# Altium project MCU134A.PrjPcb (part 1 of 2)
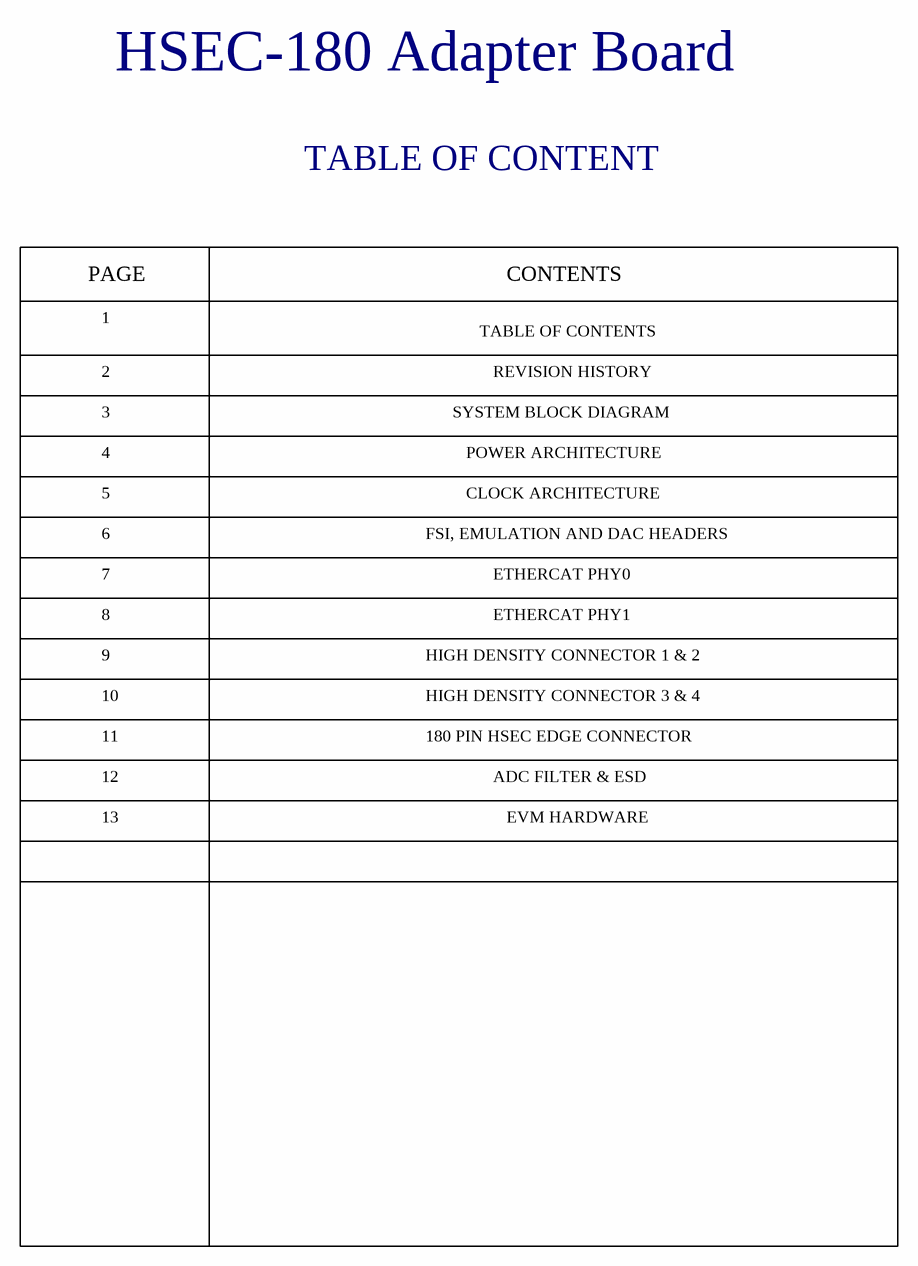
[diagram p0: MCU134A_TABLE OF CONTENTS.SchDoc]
DrawnBy: Texas Instruments; EVM_orderable: HSEC180ADAPEVM; PCB_Rev: A; PRJ_Customer: Public Release; PRJ_Engineer: Martinez Gustavo; PRJ_Number: MCU134; PRJ_Title: HSEC-180 Adapter Board; SCH_REV: A
13 sheets, 219 parts. Net scope: global (net labels, ports and power ports of the same name join across sheets).
Board file: MCU134A.PcbDoc
Sheets:
  MCU134A_TABLE OF CONTENTS.SchDoc
  MCU134A_REVISION_HISTORY.SchDoc
  MCU134A_System_Block_Diagram.SchDoc
  MCU134A_Power_Architecture.SchDoc
  MCU134A_Clock_Architecture.SchDoc
  MCU134A_FSI_Header.SchDoc
  MCU134A_EtherCAT_PHY_0.SchDoc
  MCU134A_EtherCAT_PHY_1.SchDoc
  MCU134A_High_Density_Conn1_2.SchDoc
  MCU134A_High_Density_Conn3_4.SchDoc
  MCU134A_180pin_Edge_Connector.SchDoc
  MCU134A_ADC.SchDoc
  MCU134A_EVM_Hardware.SchDoc

## Sheet MCU134A_TABLE OF CONTENTS.SchDoc
size 431 x 279 mm; Date: Not shown in title block; ApprovedBy: Not shown in title block; CheckedBy: Not shown in title block; Author: Not shown in title block; CompanyName: Not shown in title block; Engineer: Not shown in title block; Organization: Not shown in title block; Address1: Not shown in title block; Address2: Not shown in title block; Address3: Not shown in title block; Address4: Not shown in title block; DocumentNumber: 1; Revision: Use project parameter SCH_Rev; SheetNumber: 1; SheetTotal: 13; PageSetup: Record=PageOptions¦CenterHorizontal=True¦CenterVertical=True¦PrintScale=1.00¦XCorrection=1.00¦YCorrection=1.00¦PrintKind=0¦BorderSize=5000000¦LeftOffset=0¦BottomOffset=0¦Orientation=2¦PaperLength=1000¦PaperWidth=1000¦Scale=100¦PaperSource=15¦PrintQuality=600¦MediaType=1¦DitherType=10¦PaperKind=Letter¦PrintScaleMode=1

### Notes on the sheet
- HSEC-180 Adapter Board
- TABLE OF CONTENT
- PAGE
- 1
- TABLE OF CONTENTS
- CONTENTS
- 2
- REVISION HISTORY
- 3
- 4
- SYSTEM BLOCK DIAGRAM
- POWER ARCHITECTURE
- 5
- 6
- FSI, EMULATION AND DAC HEADERS
- CLOCK ARCHITECTURE
- 7
- ETHERCAT PHY0
- 9
- 8
- HIGH DENSITY CONNECTOR 1 & 2
- ETHERCAT PHY1
- 10
- 11
- HIGH DENSITY CONNECTOR 3 & 4
- 180 PIN HSEC EDGE CONNECTOR
- 12
- ADC FILTER & ESD
- 13
- EVM HARDWARE

## Sheet MCU134A_REVISION_HISTORY.SchDoc
size 431 x 279 mm; Date: Not shown in title block; ApprovedBy: Not shown in title block; CheckedBy: Not shown in title block; Author: Not shown in title block; CompanyName: Not shown in title block; Engineer: Not shown in title block; Organization: Not shown in title block; Address1: Not shown in title block; Address2: Not shown in title block; Address3: Not shown in title block; Address4: Not shown in title block; DocumentNumber: 2; Revision: Use project parameter SCH_Rev; SheetNumber: 2; SheetTotal: 13; PageSetup: Record=PageOptions¦CenterHorizontal=True¦CenterVertical=True¦PrintScale=1.00¦XCorrection=1.00¦YCorrection=1.00¦PrintKind=0¦BorderSize=5000000¦LeftOffset=0¦BottomOffset=0¦Orientation=2¦PaperLength=1000¦PaperWidth=1000¦Scale=100¦PaperSource=15¦PrintQuality=600¦MediaType=1¦DitherType=10¦PaperKind=Letter¦PrintScaleMode=1
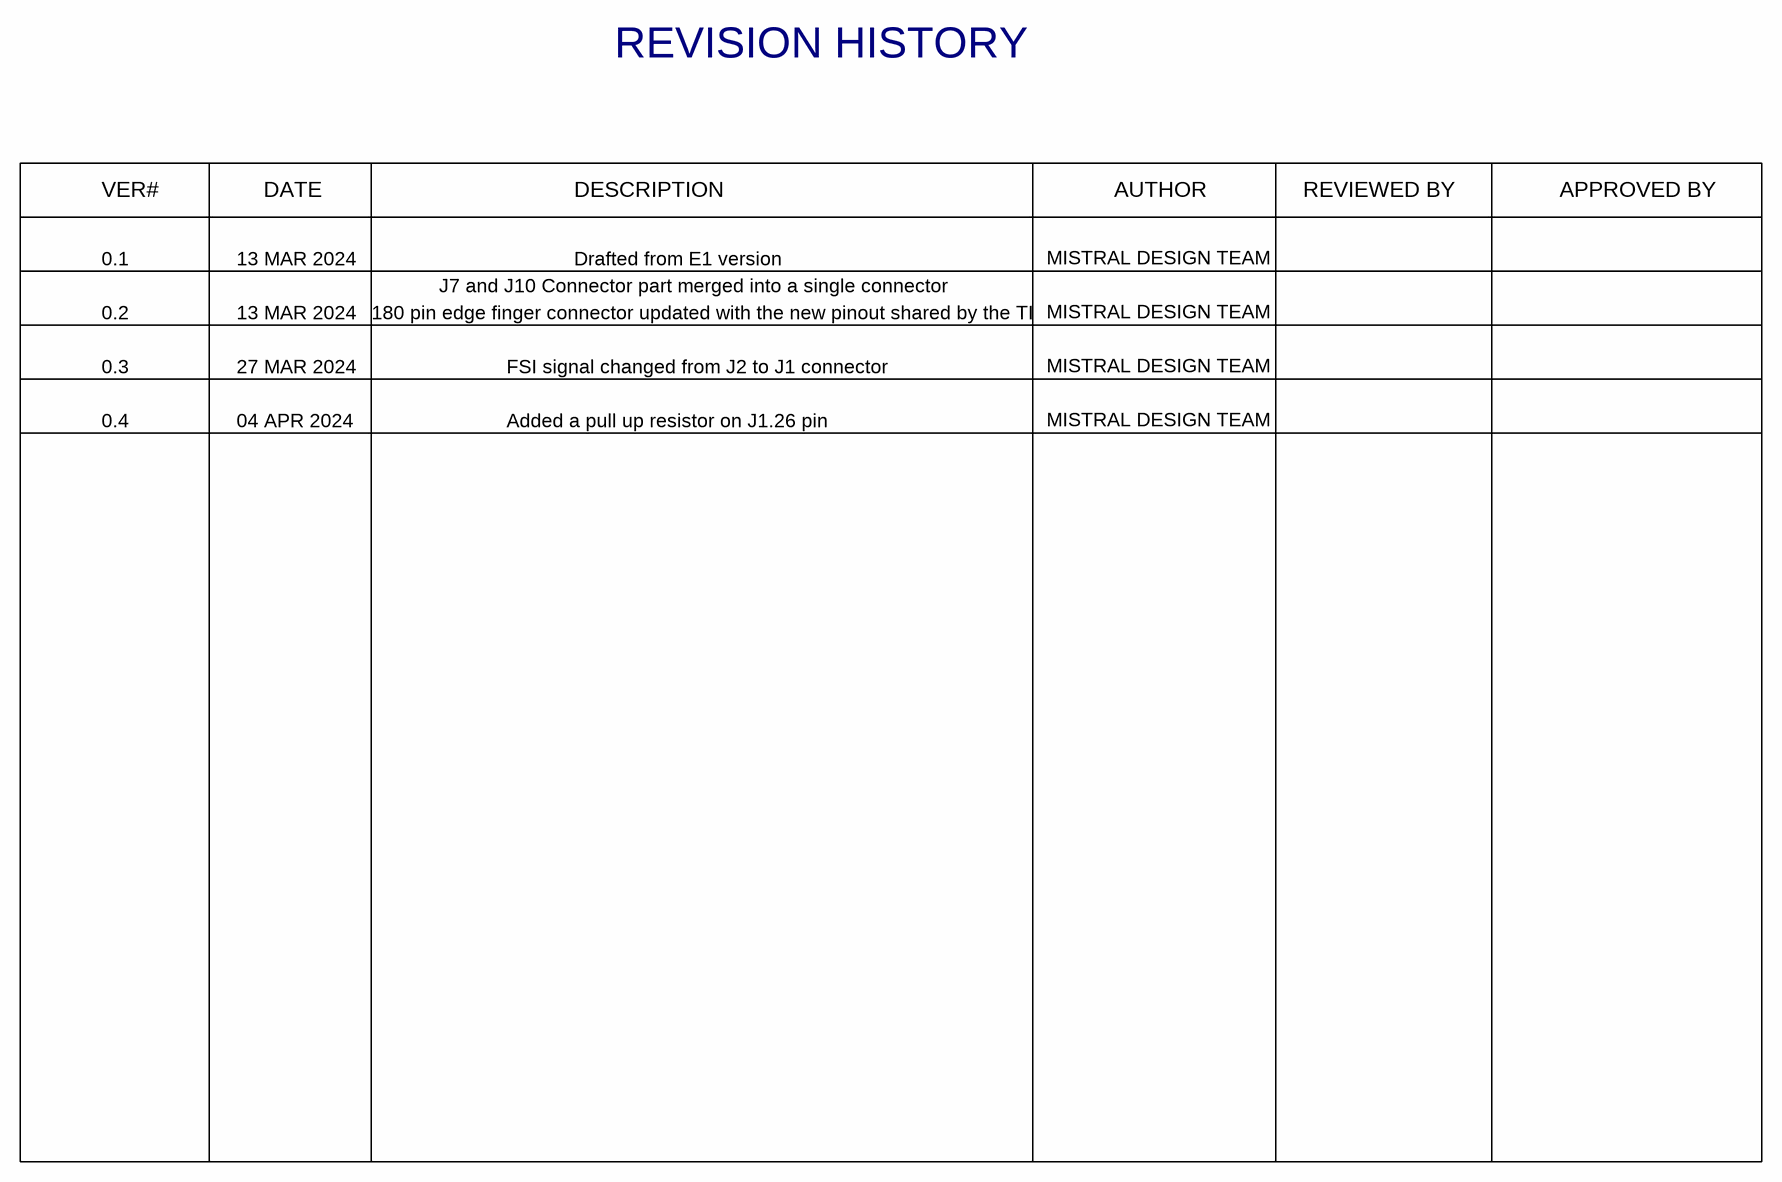
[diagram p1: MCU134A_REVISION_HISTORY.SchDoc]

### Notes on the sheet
- REVISION HISTORY
- VER#
- DATE
- DESCRIPTION
- MISTRAL DESIGN TEAM
- AUTHOR
- REVIEWED BY
- APPROVED BY
- 0.1
- 0.2
- 13 MAR 2024
- 180 pin edge finger connector updated with the new pinout shared by the TI
- J7 and J10 Connector part merged into a single connector
- Drafted from E1 version
- 0.3
- 27 MAR 2024
- FSI signal changed from J2 to J1 connector
- 0.4
- 04 APR 2024
- Added a pull up resistor on J1.26 pin

## Sheet MCU134A_System_Block_Diagram.SchDoc
size 431 x 279 mm; Date: Not shown in title block; ApprovedBy: Not shown in title block; CheckedBy: Not shown in title block; Author: Not shown in title block; CompanyName: Not shown in title block; Engineer: Not shown in title block; Organization: Not shown in title block; Address1: Not shown in title block; Address2: Not shown in title block; Address3: Not shown in title block; Address4: Not shown in title block; DocumentNumber: 3; Revision: Use project parameter SCH_Rev; SheetNumber: 3; SheetTotal: 13; PageSetup: Record=PageOptions¦CenterHorizontal=True¦CenterVertical=True¦PrintScale=1.00¦XCorrection=1.00¦YCorrection=1.00¦PrintKind=0¦BorderSize=5000000¦LeftOffset=0¦BottomOffset=0¦Orientation=2¦PaperLength=1000¦PaperWidth=1000¦Scale=100¦PaperSource=15¦PrintQuality=600¦MediaType=1¦DitherType=10¦PaperKind=Letter¦PrintScaleMode=1
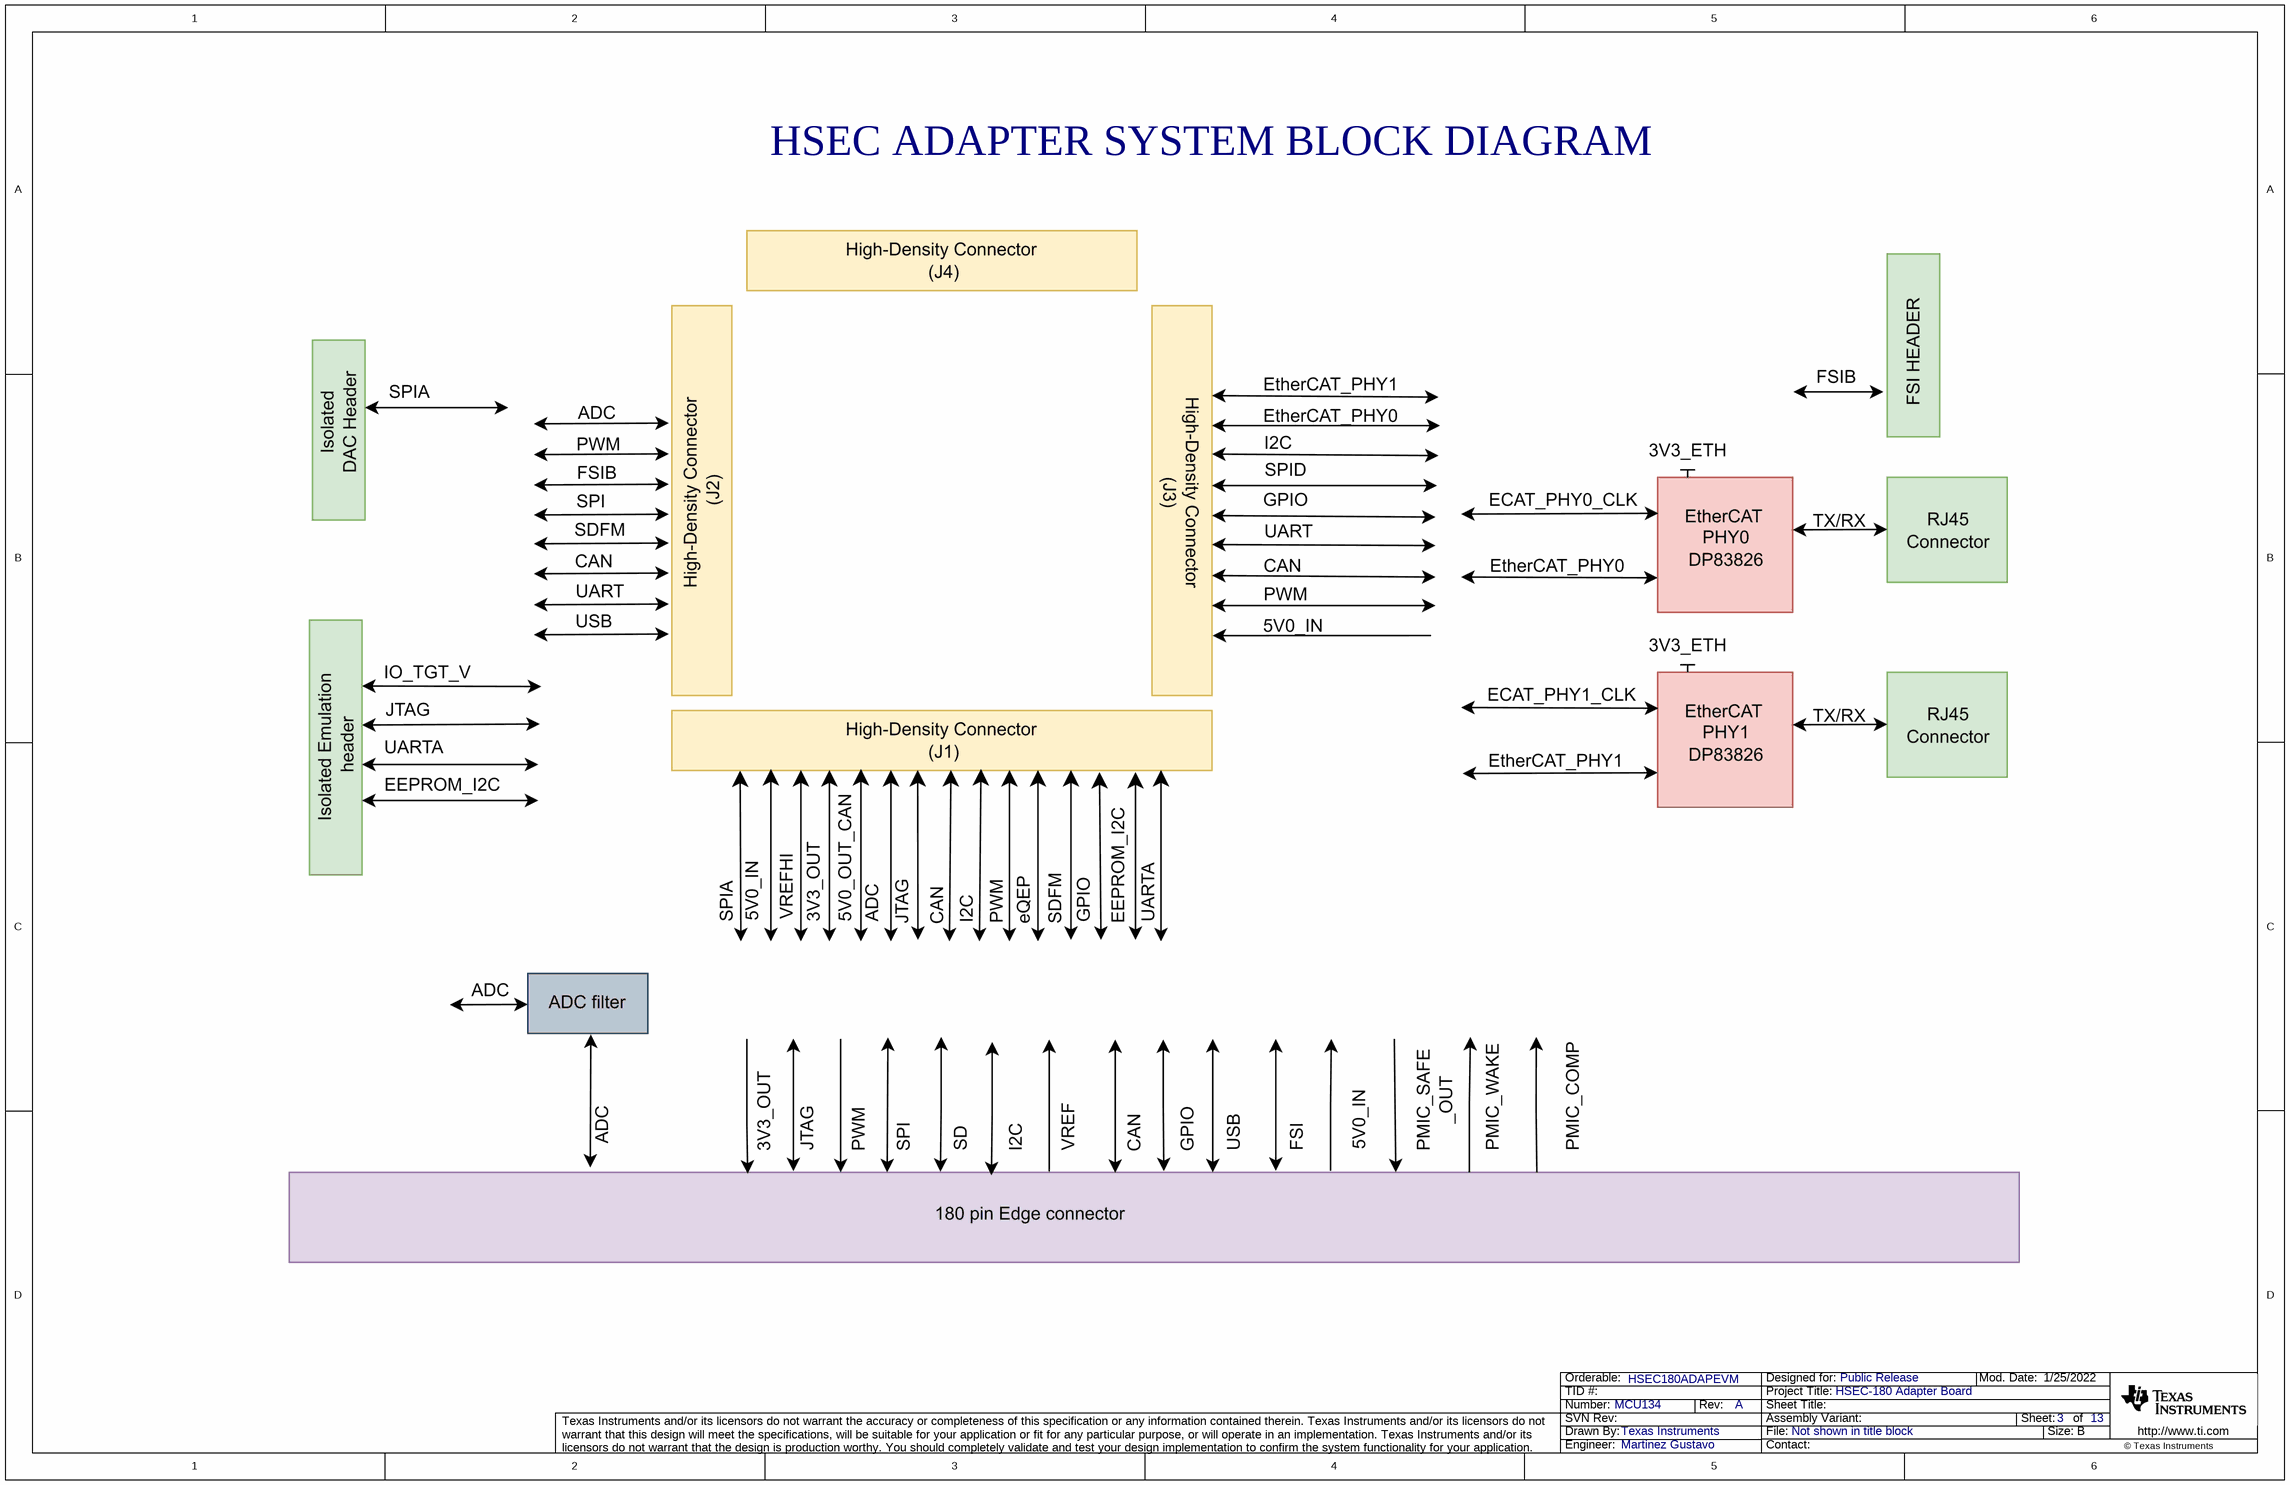
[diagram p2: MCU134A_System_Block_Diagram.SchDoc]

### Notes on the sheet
- HSEC ADAPTER SYSTEM BLOCK DIAGRAM

## Sheet MCU134A_Power_Architecture.SchDoc
size 431 x 279 mm; Date: Not shown in title block; ApprovedBy: Not shown in title block; CheckedBy: Not shown in title block; Author: Not shown in title block; CompanyName: Not shown in title block; Engineer: Not shown in title block; Organization: Not shown in title block; Address1: Not shown in title block; Address2: Not shown in title block; Address3: Not shown in title block; Address4: Not shown in title block; DocumentNumber: 4; Revision: Use project parameter SCH_Rev; SheetNumber: 4; SheetTotal: 13; PageSetup: Record=PageOptions¦CenterHorizontal=True¦CenterVertical=True¦PrintScale=1.00¦XCorrection=1.00¦YCorrection=1.00¦PrintKind=0¦BorderSize=5000000¦LeftOffset=0¦BottomOffset=0¦Orientation=2¦PaperLength=1000¦PaperWidth=1000¦Scale=100¦PaperSource=15¦PrintQuality=600¦MediaType=1¦DitherType=10¦PaperKind=Letter¦PrintScaleMode=1
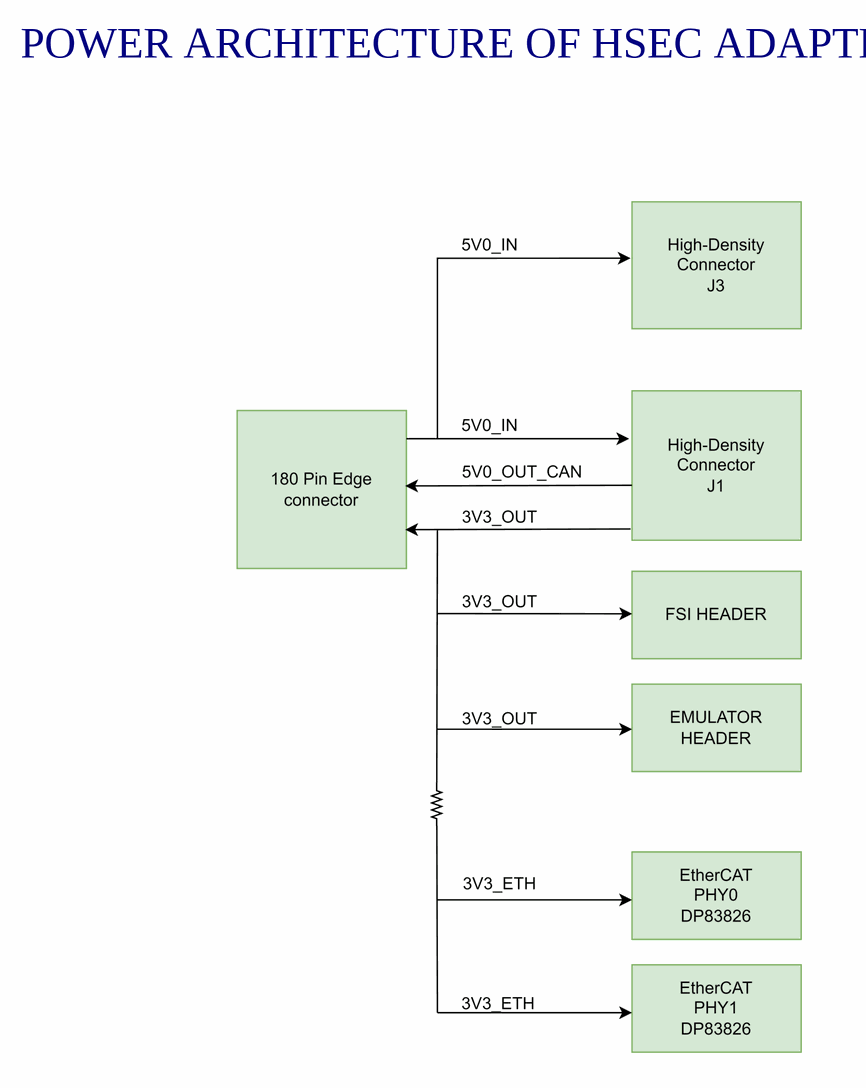
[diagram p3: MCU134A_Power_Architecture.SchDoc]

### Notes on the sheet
- POWER ARCHITECTURE OF HSEC ADAPTER

## Sheet MCU134A_Clock_Architecture.SchDoc
size 431 x 279 mm; Date: Not shown in title block; ApprovedBy: Not shown in title block; CheckedBy: Not shown in title block; Author: Not shown in title block; CompanyName: Not shown in title block; Engineer: Not shown in title block; Organization: Not shown in title block; Address1: Not shown in title block; Address2: Not shown in title block; Address3: Not shown in title block; Address4: Not shown in title block; DocumentNumber: 5; Revision: Use project parameter SCH_Rev; SheetNumber: 5; SheetTotal: 13; PageSetup: Record=PageOptions¦CenterHorizontal=True¦CenterVertical=True¦PrintScale=1.00¦XCorrection=1.00¦YCorrection=1.00¦PrintKind=0¦BorderSize=5000000¦LeftOffset=0¦BottomOffset=0¦Orientation=2¦PaperLength=1000¦PaperWidth=1000¦Scale=100¦PaperSource=15¦PrintQuality=600¦MediaType=1¦DitherType=10¦PaperKind=Letter¦PrintScaleMode=1
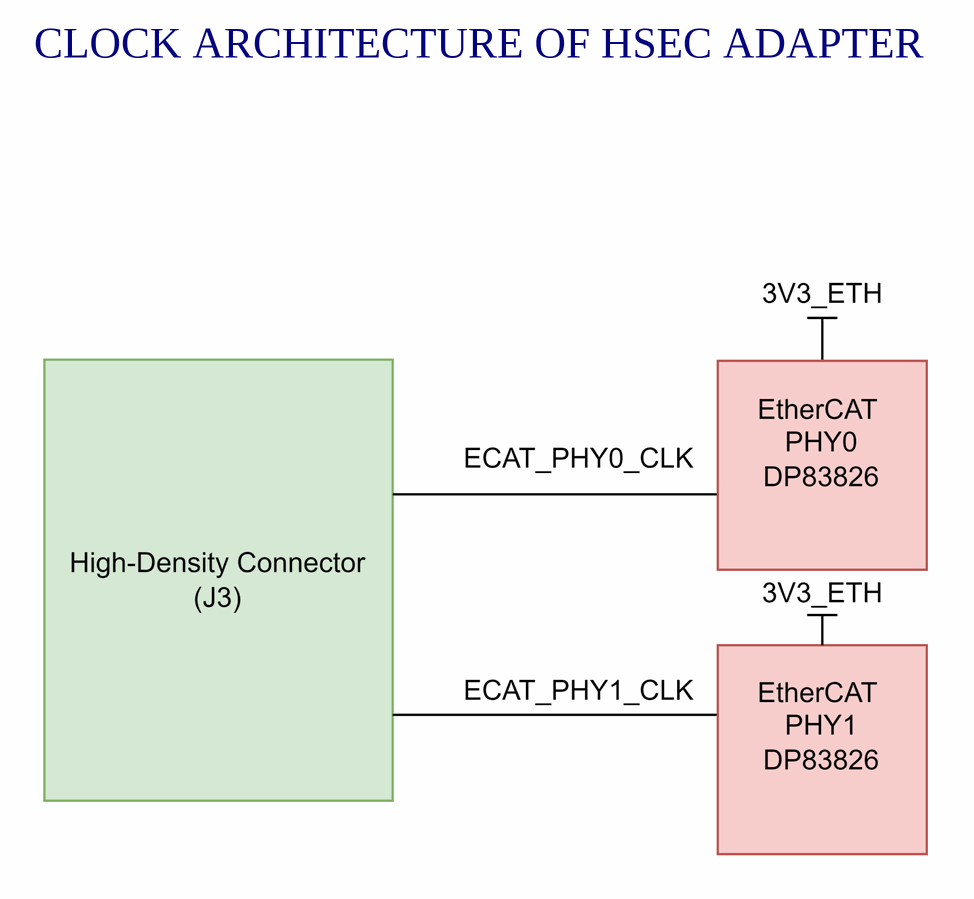
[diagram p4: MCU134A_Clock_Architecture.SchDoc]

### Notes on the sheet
- CLOCK ARCHITECTURE OF HSEC ADAPTER

## Sheet MCU134A_FSI_Header.SchDoc
size 431 x 279 mm; SheetNumber: 6; SheetTotal: 13
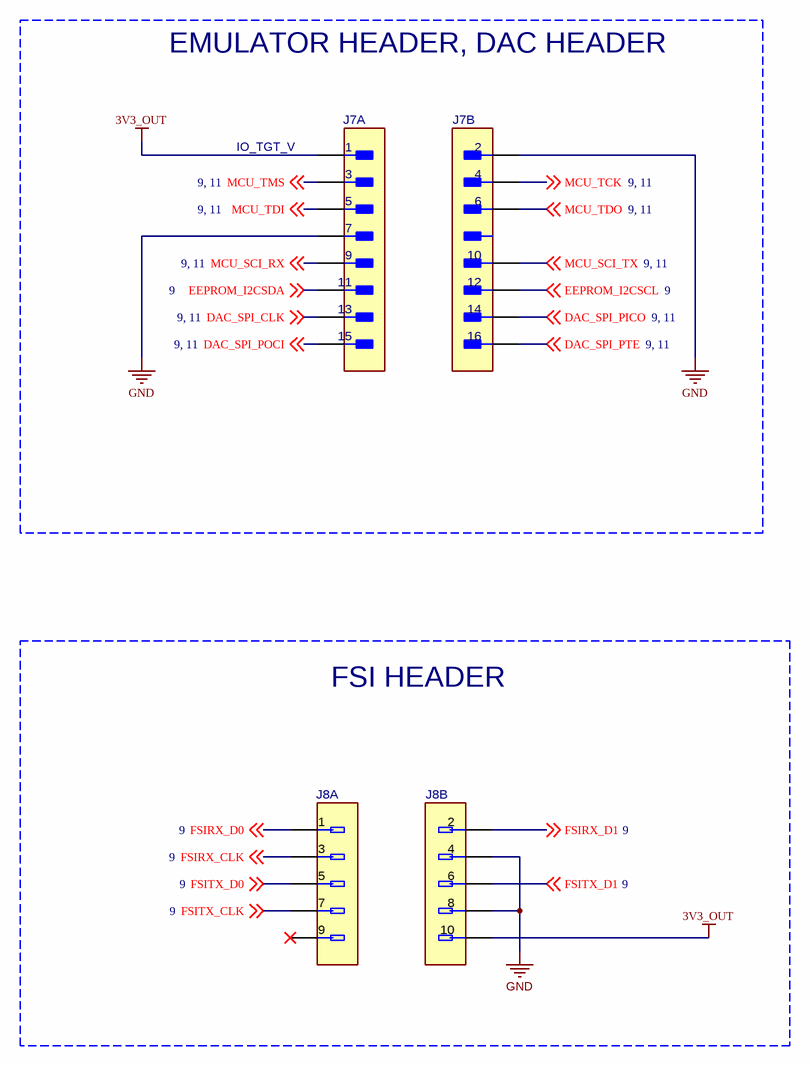
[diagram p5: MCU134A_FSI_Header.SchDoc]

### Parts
J7  TSW-108-08-G-D-RA-008  [FP-TSW-108-08-G-D-RA-008_HDR15-MFG]  (value not drawn)  (parts A,B of 2)
J8  TMM-105-01-T-D  [FP-TMM-105-01-T-D_HDR10-MFG]  (value not drawn)  (parts A,B of 2)

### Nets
3V3_OUT: J7.1 J8.10
GND: J7.2 J7.7 J8.4 J8.8
DAC_SPI_CLK: J7.13 ; off-sheet DAC_SPI_CLK
DAC_SPI_PICO: J7.14 ; off-sheet DAC_SPI_PICO
DAC_SPI_POCI: J7.15 ; off-sheet DAC_SPI_POCI
DAC_SPI_PTE: J7.16 ; off-sheet DAC_SPI_PTE
EEPROM_I2CSCL: J7.12 ; off-sheet EEPROM_I2CSCL
EEPROM_I2CSDA: J7.11 ; off-sheet EEPROM_I2CSDA
FSIRX_CLK: J8.3 ; off-sheet FSIRX_CLK
FSIRX_D0: J8.1 ; off-sheet FSIRX_D0
FSIRX_D1: J8.2 ; off-sheet FSIRX_D1
FSITX_CLK: J8.7 ; off-sheet FSITX_CLK
FSITX_D0: J8.5 ; off-sheet FSITX_D0
FSITX_D1: J8.6 ; off-sheet FSITX_D1
MCU_SCI_RX: J7.9 ; off-sheet MCU_SCI_RX
MCU_SCI_TX: J7.10 ; off-sheet MCU_SCI_TX
MCU_TCK: J7.4 ; off-sheet MCU_TCK
MCU_TDI: J7.5 ; off-sheet MCU_TDI
MCU_TDO: J7.6 ; off-sheet MCU_TDO
MCU_TMS: J7.3 ; off-sheet MCU_TMS

Not connected (* = marked no-connect by the designer): J8 9*

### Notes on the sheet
- EMULATOR HEADER, DAC HEADER
- IO_TGT_V
- FSI HEADER

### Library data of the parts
J7 = CMP-0121702-1: Connector Header Through Hole, Right Angle 16 position 0.100" (2.54mm); Manufacturer: Samtec; ContactFinish: Gold,Nickel; Row_Count: 2; AEC Qualified: No; Conn Gender: Male; SizeZ_mm: 5.21mm
J8 = CMP-0086568-1: Board-To-Board Connector, TMM Series, 10 Contacts, Header, 2 mm, Through Hole, 2 Rows; Manufacturer: Samtec; ContactFinish: Tin,Nickel; Voltage_V: 281V; Symbol Name: SYM-TMM-105-01-T-D; Row_Count: 2; Current_A: 3.2A

## Sheet MCU134A_EtherCAT_PHY_0.SchDoc
size 431 x 279 mm; SheetNumber: 7; SheetTotal: 13
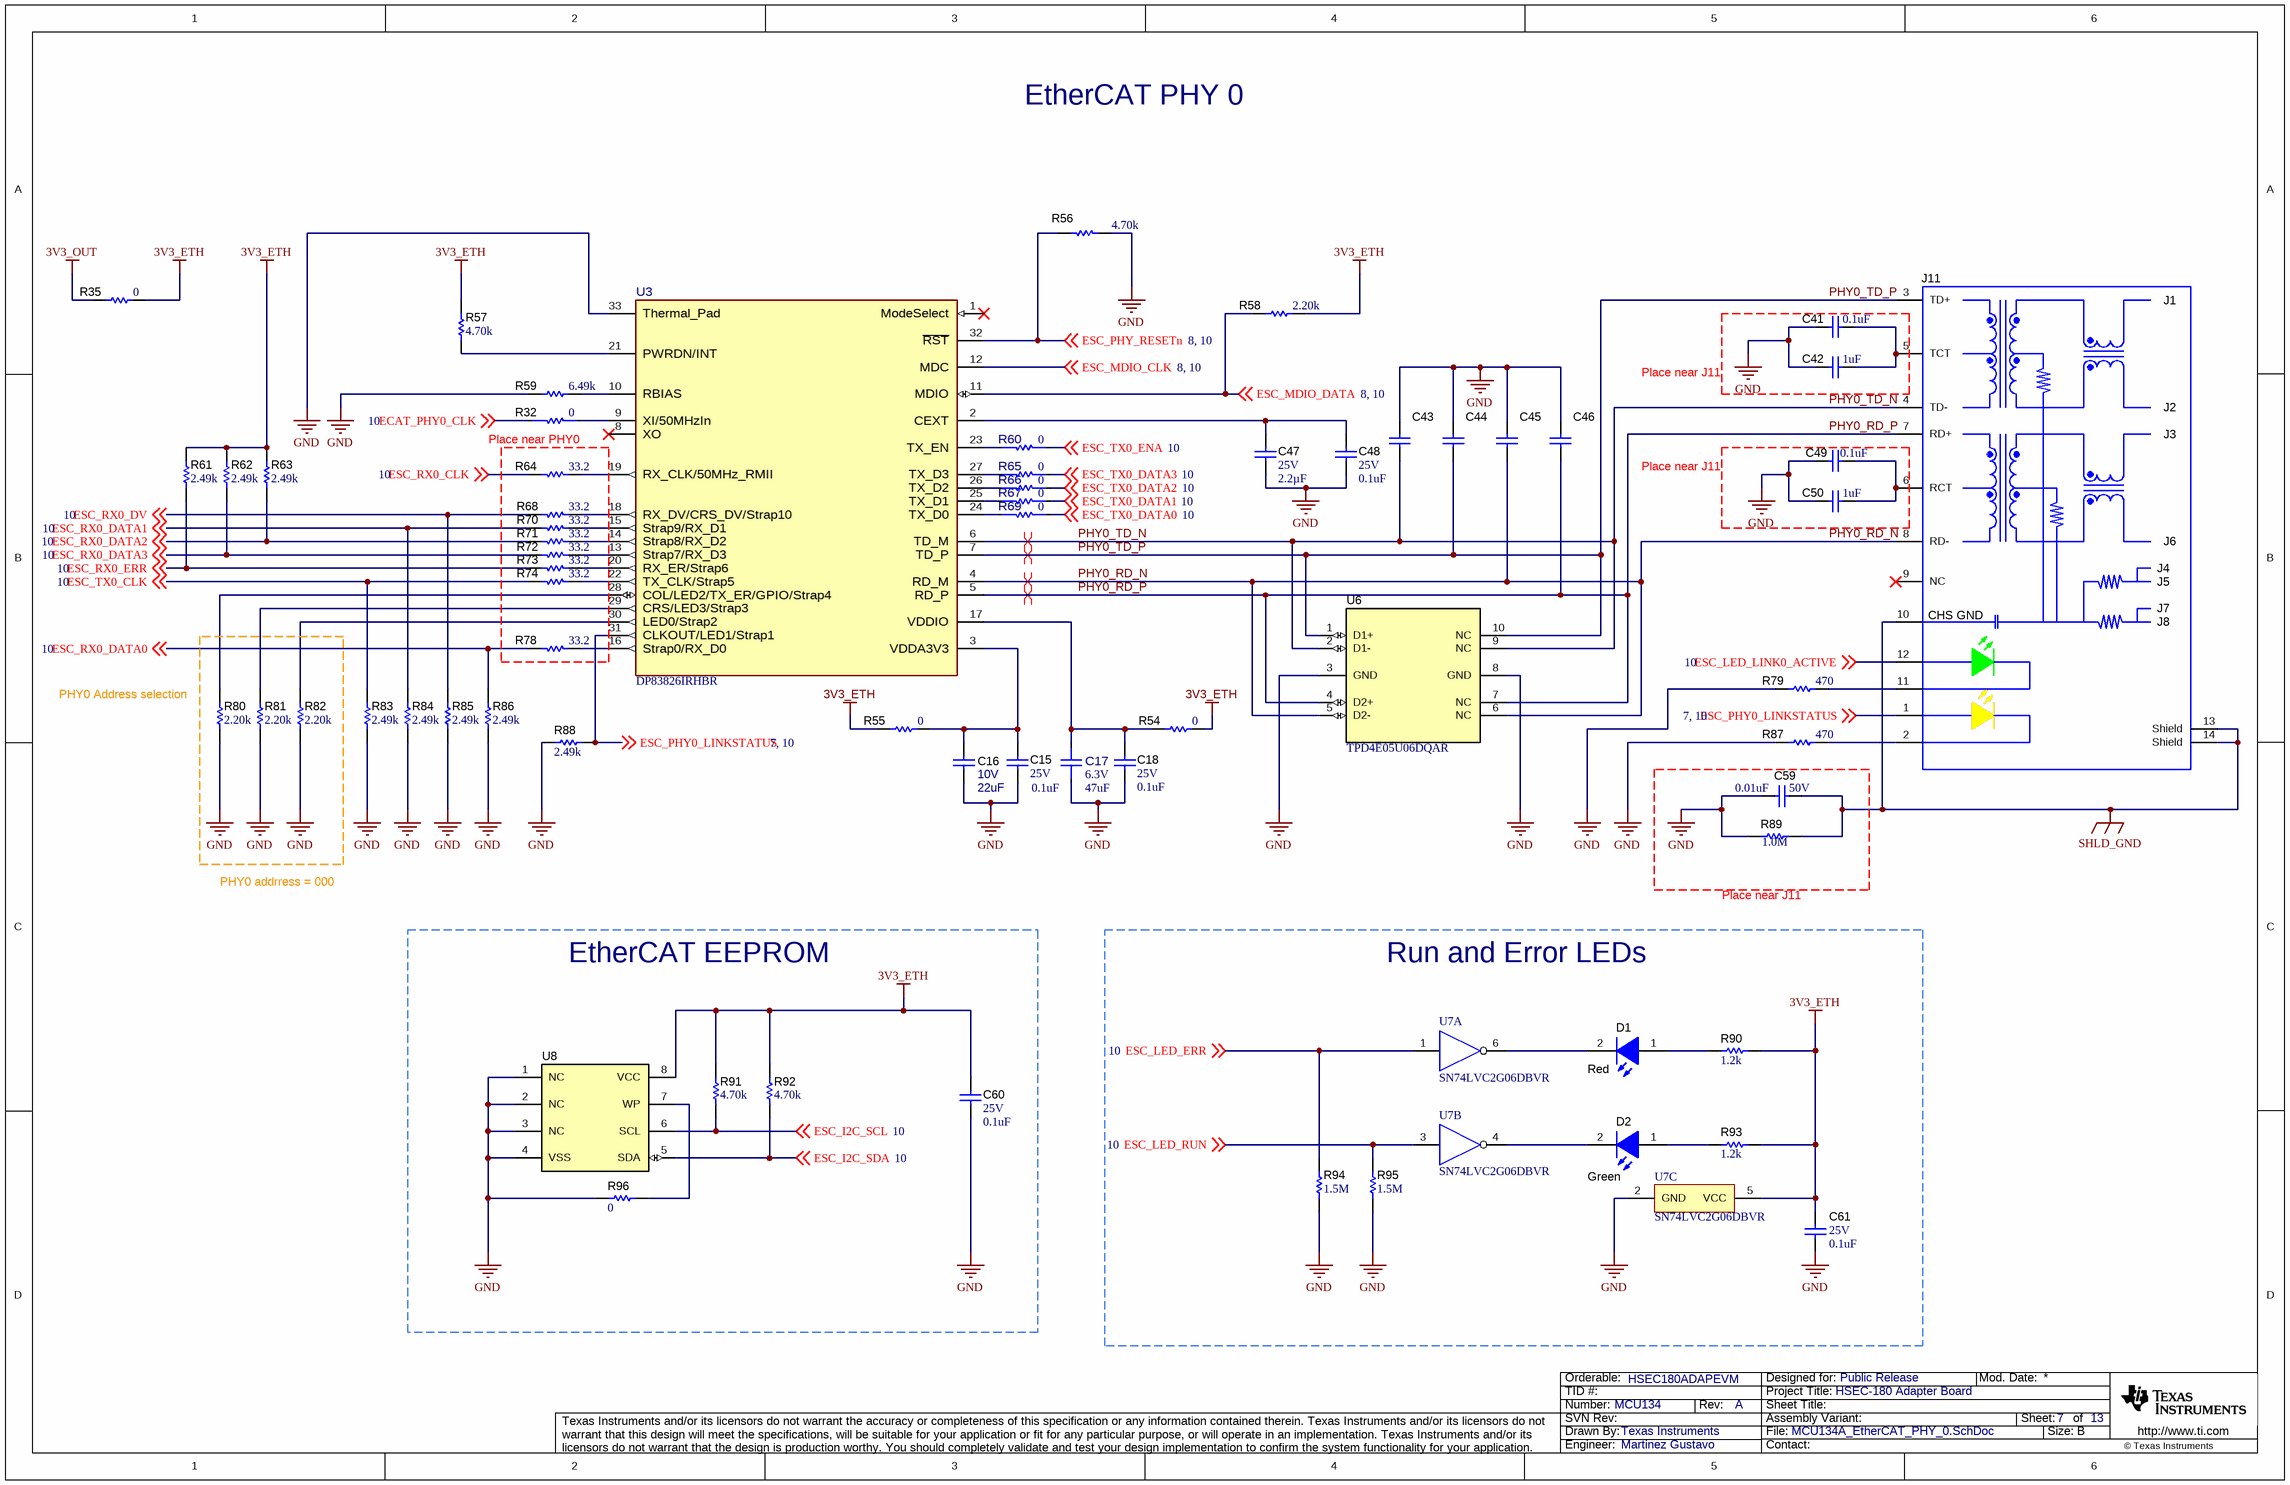
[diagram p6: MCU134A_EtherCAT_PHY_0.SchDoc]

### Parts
C15  VDC_V: 25V  ValueDisplayed: 0.1uF  [0402]  (hidden comment: GRM155R71E104KE14D)
C16  VDC_V: 10V  ValueDisplayed: 22uF  [0603]  (hidden comment: GRM188R61A226ME15D)
C17  VDC_V: 6.3V  ValueDisplayed: 47uF  [FP-GRM188R60J476ME01D_0603-MFG]  (hidden comment: GRM188R60J476ME01D)
C18  VDC_V: 25V  ValueDisplayed: 0.1uF  [0402]  (hidden comment: GRM155R71E104KE14D)
C41  ValueDisplayed: 0.1uF  [0402]  (hidden comment: GRM155R71E104KE14D)
C42  value 1uF  [0402]  (hidden comment: GRM155R61E105KE11D)
C43  GJM1555C1H4R7BB01D  [0402]  (value not drawn)
C44  GJM1555C1H4R7BB01D  [0402]  (value not drawn)
C45  GJM1555C1H4R7BB01D  [0402]  (value not drawn)
C46  GJM1555C1H4R7BB01D  [0402]  (value not drawn)
C47  VDC_V: 25V  ValueDisplayed: 2.2µF  [0402]  (hidden comment: GRM155R61E225ME15D)
C48  VDC_V: 25V  ValueDisplayed: 0.1uF  [0402]  (hidden comment: GRM155R71E104KE14D)
C49  ValueDisplayed: 0.1uF  [0402]  (hidden comment: GRM155R71E104KE14D)
C50  value 1uF  [0402]  (hidden comment: GRM155R61E105KE11D)
C59  VDC_V: 50V  ValueDisplayed: 0.01uF  [0805_HV]  (hidden comment: GRM2195C1H103JA01D)
C60  VDC_V: 25V  ValueDisplayed: 0.1uF  [0402]  (hidden comment: GRM155R71E104KE14D)
C61  VDC_V: 25V  ValueDisplayed: 0.1uF  [0402]  (hidden comment: GRM155R71E104KE14D)
D1  value Red  [APHHS1005_Red]  (hidden comment: APHHS1005SURCK)
D2  value Green  [APHHS1005_Green]  (hidden comment: APHHS1005CGCK)
J11  7498010210A  [Wurth_7498010210A]  (value not drawn)
R32  value 0  [FP-CRCW04020000Z0EDHP_0402-MFG]  (hidden comment: CRCW04020000Z0EDHP)
R35  ValueDisplayed: 0  [0603]  (hidden comment: ERJ-3GEY0R00V)
R54  ValueDisplayed: 0  [0603]  (hidden comment: ERJ-3GEY0R00V)
R55  ValueDisplayed: 0  [0603]  (hidden comment: ERJ-3GEY0R00V)
R56  ValueDisplayed: 4.70k  [0402]  (hidden comment: CRG0402F4K7)
R57  ValueDisplayed: 4.70k  [0402]  (hidden comment: CRG0402F4K7)
R58  ValueDisplayed: 2.20k  [0402]  (hidden comment: CRCW04022K20FKED)
R59  ValueDisplayed: 6.49k  [0402]  (hidden comment: CRCW04026K49FKED)
R60  value 0  [FP-CRCW04020000Z0EDHP_0402-MFG]  (hidden comment: CRCW04020000Z0EDHP)
R61  ValueDisplayed: 2.49k  [0402]  (hidden comment: CRCW04022K49FKED)
R62  ValueDisplayed: 2.49k  [0402]  (hidden comment: CRCW04022K49FKED)
R63  ValueDisplayed: 2.49k  [0402]  (hidden comment: CRCW04022K49FKED)
R64  ValueDisplayed: 33.2  [0402]  (hidden comment: CRCW040233R2FKED)
R65  value 0  [FP-CRCW04020000Z0EDHP_0402-MFG]  (hidden comment: CRCW04020000Z0EDHP)
R66  value 0  [FP-CRCW04020000Z0EDHP_0402-MFG]  (hidden comment: CRCW04020000Z0EDHP)
R67  value 0  [FP-CRCW04020000Z0EDHP_0402-MFG]  (hidden comment: CRCW04020000Z0EDHP)
R68  ValueDisplayed: 33.2  [0402]  (hidden comment: CRCW040233R2FKED)
R69  value 0  [FP-CRCW04020000Z0EDHP_0402-MFG]  (hidden comment: CRCW04020000Z0EDHP)
R70  ValueDisplayed: 33.2  [0402]  (hidden comment: CRCW040233R2FKED)
R71  ValueDisplayed: 33.2  [0402]  (hidden comment: CRCW040233R2FKED)
R72  ValueDisplayed: 33.2  [0402]  (hidden comment: CRCW040233R2FKED)
R73  ValueDisplayed: 33.2  [0402]  (hidden comment: CRCW040233R2FKED)
R74  ValueDisplayed: 33.2  [0402]  (hidden comment: CRCW040233R2FKED)
R78  ValueDisplayed: 33.2  [0402]  (hidden comment: CRCW040233R2FKED)
R79  ValueDisplayed: 470  [0603]  (hidden comment: CRCW0603470RJNEA)
R80  ValueDisplayed: 2.20k  [0402]  (hidden comment: CRCW04022K20FKED)
R81  ValueDisplayed: 2.20k  [0402]  (hidden comment: CRCW04022K20FKED)
R82  ValueDisplayed: 2.20k  [0402]  (hidden comment: CRCW04022K20FKED)
R83  ValueDisplayed: 2.49k  [0402]  (hidden comment: CRCW04022K49FKED)
R84  ValueDisplayed: 2.49k  [0402]  (hidden comment: CRCW04022K49FKED)
R85  ValueDisplayed: 2.49k  [0402]  (hidden comment: CRCW04022K49FKED)
R86  ValueDisplayed: 2.49k  [0402]  (hidden comment: CRCW04022K49FKED)
R87  ValueDisplayed: 470  [0603]  (hidden comment: CRCW0603470RJNEA)
R88  ValueDisplayed: 2.49k  [0402]  (hidden comment: CRCW04022K49FKED)
R89  ValueDisplayed: 1.0M  [0805_HV]  (hidden comment: ERJ-6GEYJ105V)
R90  ValueDisplayed: 1.2k  [0402]  (hidden comment: CRCW04021K20JNED)
R91  ValueDisplayed: 4.70k  [0402]  (hidden comment: CRG0402F4K7)
R92  ValueDisplayed: 4.70k  [0402]  (hidden comment: CRG0402F4K7)
R93  ValueDisplayed: 1.2k  [0402]  (hidden comment: CRCW04021K20JNED)
R94  ValueDisplayed: 1.5M  [0402]  (hidden comment: CRCW04021M50JNED)
R95  ValueDisplayed: 1.5M  [0402]  (hidden comment: CRCW04021M50JNED)
R96  ValueDisplayed: 0  [0402]  (hidden comment: CRCW04020000Z0ED)
U3  DP83826IRHBR  [RHB0032M-MFG]
U6  TPD4E05U06DQAR  [DQA0010A]
U7  SN74LVC2G06DBVR  [DBV0006A_N]  (parts A,B,C of 3)
U8  CAT24C16WI-GT3  [SOIC-8]  (value not drawn)

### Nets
3V3_ETH: C60.1 C61.1 R35.2 R54.2 R55.1 R57.1 R58.1 R61.2 R62.2 R63.2 R90.1 R91.2 R92.2 R93.1 U7.5(VCC) U8.8(VCC)
3V3_OUT: R35.1
GND: C15.2 C16.2 C17.1 C18.2 C41.2 C42.2 C43.1 C44.1 C45.1 C46.1 C47.2 C48.2 C49.2 C50.2 C59.2 C60.2 C61.2 R56.2 R59.1 R79.1 R80.1 R81.1 R82.1 R83.1 R84.1 R85.1 R86.1 R87.1 R88.1 R89.1 R94.2 R95.2 R96.2 U3.33(Thermal_Pad) U6.3(GND) U6.8(GND) U7.2(GND) U8.1(NC) U8.2(NC) U8.3(NC) U8.4(VSS)
SHLD_GND: C59.1 J11.10(CHS_GND) J11.13(Shield) J11.14(Shield) R89.2
ECAT_PHY0_CLK: R32.1 ; off-sheet ECAT_PHY0_CLK
ESC_I2C_SCL: R91.1 U8.6(SCL) ; off-sheet ESC_I2C_SCL
ESC_I2C_SDA: R92.1 U8.5(SDA) ; off-sheet ESC_I2C_SDA
ESC_LED_ERR: R94.1 U7.1(1A) ; off-sheet ESC_LED_ERR
ESC_LED_LINK0_ACTIVE: J11.12(LEFT_LED_ANODE) ; off-sheet ESC_LED_LINK0_ACTIVE
ESC_LED_RUN: R95.1 U7.3(2A) ; off-sheet ESC_LED_RUN
ESC_MDIO_CLK: U3.12(MDC) ; off-sheet ESC_MDIO_CLK
ESC_MDIO_DATA: R58.2 U3.11(MDIO) ; off-sheet ESC_MDIO_DATA
ESC_PHY0_LINKSTATUS: J11.1(RIGHT_LED_ANODE) R88.2 U3.31(CLKOUT/LED1/Strap1) ; off-sheet ESC_PHY0_LINKSTATUS
ESC_PHY_RESETn: R56.1 U3.32(~{RST}) ; off-sheet ESC_PHY_RESETn
ESC_RX0_CLK: R64.1 ; off-sheet ESC_RX0_CLK
ESC_RX0_DATA0: R78.1 R86.2 ; off-sheet ESC_RX0_DATA0
ESC_RX0_DATA1: R70.1 R84.2 ; off-sheet ESC_RX0_DATA1
ESC_RX0_DATA2: R63.1 R71.1 ; off-sheet ESC_RX0_DATA2
ESC_RX0_DATA3: R62.1 R72.1 ; off-sheet ESC_RX0_DATA3
ESC_RX0_DV: R68.1 R85.2 ; off-sheet ESC_RX0_DV
ESC_RX0_ERR: R61.1 R73.1 ; off-sheet ESC_RX0_ERR
ESC_TX0_CLK: R74.1 R83.2 ; off-sheet ESC_TX0_CLK
ESC_TX0_DATA0: R69.2 ; off-sheet ESC_TX0_DATA0
ESC_TX0_DATA1: R67.2 ; off-sheet ESC_TX0_DATA1
ESC_TX0_DATA2: R66.2 ; off-sheet ESC_TX0_DATA2
ESC_TX0_DATA3: R65.2 ; off-sheet ESC_TX0_DATA3
ESC_TX0_ENA: R60.2 ; off-sheet ESC_TX0_ENA
PHY0_RD_N: C45.2 J11.8(RD-) U3.4(RD_M) U6.5(D2-) U6.6(NC)
PHY0_RD_P: C46.2 J11.7(RD+) U3.5(RD_P) U6.4(D2+) U6.7(NC)
PHY0_TD_N: C43.2 J11.4(TD-) U3.6(TD_M) U6.2(D1-) U6.9(NC)
PHY0_TD_P: C44.2 J11.3(TD+) U3.7(TD_P) U6.1(D1+) U6.10(NC)
NetC15_1: C15.1 C16.1 R55.2 U3.3(VDDA3V3)
NetC17_2: C17.2 C18.1 R54.1 U3.17(VDDIO)
NetC41_1: C41.1 C42.1 J11.5(TCT)
NetC47_1: C47.1 C48.1 U3.2(CEXT)
NetC49_1: C49.1 C50.1 J11.6(RCT)
NetD1_1: D1.1(A) R90.2
NetD1_2: D1.2(K) U7.6(1Y)
NetD2_1: D2.1(A) R93.2
NetD2_2: D2.2(K) U7.4(2Y)
NetJ11_2: J11.2(RIGHT_LED_CATHODE) R87.2
NetJ11_11: J11.11(LEFT_LED_CATHODE) R79.2
NetR32_2: R32.2 U3.9(XI/50MHzIn)
NetR57_2: R57.2 U3.21(PWRDN/INT)
NetR59_2: R59.2 U3.10(RBIAS)
NetR60_1: R60.1 U3.23(TX_EN)
NetR64_2: R64.2 U3.19(RX_CLK/50MHz_RMII)
NetR65_1: R65.1 U3.27(TX_D3)
NetR66_1: R66.1 U3.26(TX_D2)
NetR67_1: R67.1 U3.25(TX_D1)
NetR68_2: R68.2 U3.18(RX_DV/CRS_DV/Strap10)
NetR69_1: R69.1 U3.24(TX_D0)
NetR70_2: R70.2 U3.15(Strap9/RX_D1)
NetR71_2: R71.2 U3.14(Strap8/RX_D2)
NetR72_2: R72.2 U3.13(Strap7/RX_D3)
NetR73_2: R73.2 U3.20(RX_ER/Strap6)
NetR74_2: R74.2 U3.22(TX_CLK/Strap5)
NetR78_2: R78.2 U3.16(Strap0/RX_D0)
NetR80_2: R80.2 U3.28(COL/LED2/TX_ER/GPIO/Strap4)
NetR81_2: R81.2 U3.29(CRS/LED3/Strap3)
NetR82_2: R82.2 U3.30(LED0/Strap2)
NetR96_1: R96.1 U8.7(WP)

Not connected (* = marked no-connect by the designer): J11 9(NC)*; U3 1(ModeSelect)* 8(XO)*

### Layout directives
differential pair: PHY0_RD_N, PHY0_RD_P, PHY0_TD_N, PHY0_TD_P

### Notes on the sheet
- EtherCAT PHY 0
- Place near J11
- (near R32) Place near PHY0
- (near R80) PHY0 Address selection
- PHY0 addrress = 000
- EtherCAT EEPROM
- Run and Error LEDs

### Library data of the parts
C15 C18 C48 C60 C61 = CMP-0006659-2: CAP, CERM, 0.1 uF, 25 V, +/- 10%, X7R, 0402; Manufacturer: MuRata; TaMin_C: -55°C; Polarized: N; SizeAreaWB_mm2: 3; Value1: Unknown; U/M: EA; Value: 0.1uF; TaMax_C: 125°C; SizeZ_mm: 0.6; SizeX_mm: 1; SizeY_mm: 0.5; Cap_F: 100nF; AEC Category: Q200
C16 = CMP-0007324-5: CAP, CERM, 22 uF, 10 V, +/- 20%, X5R, 0603; Manufacturer: MuRata; TaMin_C: -55°C; Polarized: N; SizeAreaWB_mm2: 4.68; Value1: Unknown; U/M: EA; Value: 22uF; TaMax_C: 85°C; SizeZ_mm: 1; SizeX_mm: 1.6; SizeY_mm: 0.8; SizeArea_mm2: 1.28; Cap_F: 22µF; AEC Category: Q200
C17 = CMP-0120208-1: Chip Multilayer Ceramic Capacitor for General Purpose 47uF ±20% 6.3V X5R SMD 0603; Manufacturer: Murata; TempCo: 15%; Value: 47µF; SizeZ_mm: 1mm; AEC Qualified: No
C41 C49 = CMP-0006659-2: CAP, CERM, 0.1 uF, 25 V, +/- 10%, X7R, 0402; Manufacturer: MuRata; TaMin_C: -55°C; Polarized: N; SizeAreaWB_mm2: 3; Value1: Unknown; U/M: EA; Value: 0.1uF; TaMax_C: 125°C; SizeZ_mm: 0.6; SizeX_mm: 1; SizeY_mm: 0.5; Value2: 25V; Cap_F: 100nF; AEC Category: Q200
C42 C50 = CMP-0086061-1: CAP, CERM, 1 µF, 25 V,+/- 10%, X5R, 0402; Manufacturer: MuRata; SizeY_mm: 0.5; TaMin_C: -55°C; VDC_V: 25V; Polarized: N; AEC Category: Q200; Cap_F: 1µF; SizeX_mm: 1; SizeAreaWB_mm2: 3; SizeZ_mm: 0.6; TaMax_C: 85°C; U/M: EA
C43-C46 = CMP-0006367-2: CAP, CERM, 4.7 pF, 50 V, +/- 2%, C0G/NP0, 0402; Manufacturer: MuRata; Value: 4.7pF; SizeZ_mm: 0.6; VDC_V: 50V; AEC Qualified: N; AEC Category: Q200; SizeArea_mm2: 0.5; SizeAreaWB_mm2: 3; SizeX_mm: 1; TaMax_C: 125°C; TaMin_C: -55°C; U/M: EA; Value1: Unknown
C47 = CMP-0081010-1: CAP, CERM, 2.2 µF, 25 V,+/- 20%, X5R, 0402; Manufacturer: MuRata; TaMin_C: -55°C; Polarized: N; SizeAreaWB_mm2: 3; U/M: EA; Value: 2.2uF; TaMax_C: 85°C; SizeZ_mm: 0.6; SizeX_mm: 1; SizeY_mm: 0.5; AEC Category: Q200
C59 = CMP-0008156-2: CAP, CERM, 0.01 uF, 50 V, +/- 5%, C0G/NP0, 0805; Manufacturer: MuRata; TaMin_C: -55°C; Polarized: N; SizeAreaWB_mm2: 6.75; Value1: Unknown; U/M: EA; Value: 0.01uF; TaMax_C: 125°C; SizeZ_mm: 1.45; SizeX_mm: 2; SizeY_mm: 1.25; Cap_Case: 0805; SizeArea_mm2: 2.5; Cap_F: 10nF; AEC Category: Q200
D1 = CMP-0067681-2: LED, Red, SMD; Manufacturer: Kingbright; Vf_V: 1.95V; SizeAreaWB_mm2: 3.0; Tjmax_C: 85°C; SizeX_mm: 1.0; Io_A: 20mA; SizeArea_mm2: 0.5; Vr_V: 5V; Value1: 0.075W; SizeZ_mm: 0.6; Angle: 120.0; Ir_A: 10µA; Power_TotalModule: 75mW
D2 = CMP-0067682-2: LED, Green, SMD; Manufacturer: Kingbright; Value1: 0.075W; Vf_V: 2.1V; Vr_V: 5V; SizeArea_mm2: 0.5; Power_TotalModule: 75mW; Tjmax_C: 85°C; Angle: 120.0; SizeAreaWB_mm2: 3.0; SizeX_mm: 1.0; Ir_A: 10µA; Io_A: 20mA; SizeZ_mm: 0.6
J11 = CMP-0086350-1: Connector, RJ45, 1x1, Gold, R/A, SMT; Manufacturer: Wurth Elektronik; Row_Count: 1; Gender: Female
R32 R60 R65-R67 R69 = CMP-0001606-1: RES Thick Film, 0Ω, 0.2W, 0402; Manufacturer: Vishay Dale; AEC Grade: Grade 0; AEC Qualified: Yes; Power_W: 200mW; SizeZ_mm: 0.4mm; VDC_V: 50V
R35 R54 R55 = CMP-0025874-4: RES, 0, 5%, 0.1 W, AEC-Q200 Grade 0, 0603; Manufacturer: Panasonic; Power_W: 100mW; TempCo: 600 ppm/C; Value_Code: 0000; Value: 0; EIA_Code: E24; SizeX_mm: 1.6; SizeY_mm: 0.8; SizeZ_mm: 1; Value2: 0.1W; SizeArea_mm2: 1.28; AEC Qualified: Y; VDC_V: 50V; AEC Category: Q200; SizeAreaWB_mm2: 4.68
R56 R57 R91 R92 = CMP-0026631-1: RES, 4.70 k, 1%, 0.063 W, 0402; Manufacturer: TE Connectivity; Power_W: 63mW; TempCo: 100 ppm/C; Value_Code: 4k70; U/M: EA; Value: 4.70k; Res_ohm: 4.7k; SizeX_mm: 1; SizeY_mm: 0.5; SizeZ_mm: 0.6; Value2: 0.063W; AEC Qualified: N; AEC Category: Q200
R58 R80-R82 = CMP-0026231-2: RES, 2.20 k, 1%, 0.063 W, AEC-Q200 Grade 0, 0402; Manufacturer: Vishay-Dale; Power_W: 63mW; TempCo: 100 ppm/C; Value_Code: 2k20; Value: 2.20k; Res_ohm: 2.2k; SizeX_mm: 1; SizeY_mm: 0.5; SizeZ_mm: 0.6; Value2: 0.063W; AEC Qualified: Y; AEC Category: Q200; AEC Grade: 0
R59 = CMP-0026515-2: RES, 6.49 k, 1%, 0.063 W, AEC-Q200 Grade 0, 0402; Manufacturer: Vishay-Dale; Power_W: 63mW; TempCo: 100 ppm/C; Value_Code: 6k49; Value: 6.49k; EIA_Code: E96; SizeX_mm: 1; SizeY_mm: 0.5; SizeZ_mm: 0.6; Value2: 0.063W; AEC Qualified: Y; VDC_V: 50V; AEC Category: Q200; AEC Grade: 0
R61-R63 R83-R86 R88 = CMP-0026237-2: RES, 2.49 k, 1%, 0.063 W, AEC-Q200 Grade 0, 0402; Manufacturer: Vishay-Dale; Power_W: 63mW; TempCo: 100 ppm/C; Value_Code: 2k49; Value: 2.49k; EIA_Code: E96; SizeX_mm: 1; SizeY_mm: 0.5; SizeZ_mm: 0.6; Value2: 0.063W; AEC Qualified: Y; VDC_V: 50V; AEC Category: Q200; AEC Grade: 0
R64 R68 R70-R74 R78 = CMP-0026299-2: RES, 33.2, 1%, 0.063 W, AEC-Q200 Grade 0, 0402; Manufacturer: Vishay-Dale; Power_W: 63mW; TempCo: 100 ppm/C; Value_Code: 33R2; Value: 33.2; EIA_Code: E96; SizeX_mm: 1; SizeY_mm: 0.5; SizeZ_mm: 0.6; Value2: 0.063W; AEC Qualified: Y; VDC_V: 50V; AEC Category: Q200; AEC Grade: 0
R79 R87 = CMP-0025813-4: RES, 470, 5%, 0.1 W, AEC-Q200 Grade 0, 0603; Manufacturer: Vishay-Dale; Power_W: 100mW; TempCo: 200 ppm/C; Value_Code: 470R; Value: 470; EIA_Code: E24; SizeX_mm: 1.6; SizeY_mm: 0.8; SizeZ_mm: 1; Value2: 0.1W; SizeArea_mm2: 1.28; AEC Qualified: Y; VDC_V: 75V; AEC Category: Q200; AEC Grade: 0
R89 = CMP-0020623-3: RES, 1.0 M, 5%, 0.125 W, AEC-Q200 Grade 0, 0805; Manufacturer: Panasonic; Power_W: 125mW; TempCo: 150 ppm/C; Value_Code: 1M00; Value: 1.0Meg; EIA_Code: E24; Res_ohm: 1M; SizeX_mm: 2; SizeY_mm: 1.25; SizeZ_mm: 1.45; Value2: 0.125W; SizeArea_mm2: 2.5; AEC Qualified: Y; VDC_V: 150V; AEC Category: Q200; AEC Grade: 0; SizeAreaWB_mm2: 6.75
R90 R93 = CMP-0026854-5: RES, 1.2 k, 5%, 0.063 W, AEC-Q200 Grade 0, 0402; Manufacturer: Vishay-Dale; Power_W: 63mW; TempCo: 200 ppm/C; Value_Code: 1k20; Value: 1.2k; EIA_Code: E24; SizeX_mm: 1; SizeY_mm: 0.5; SizeZ_mm: 0.6; Value2: 0.063W; AEC Qualified: Y; VDC_V: 50V; AEC Category: Q200; AEC Grade: 0
R94 R95 = CMP-0026863-2: RES, 1.5 M, 5%, 0.063 W, AEC-Q200 Grade 0, 0402; Manufacturer: Vishay-Dale; Power_W: 63mW; TempCo: 200 ppm/C; Value_Code: 1M50; Value: 1.5Meg; EIA_Code: E24; SizeX_mm: 1; SizeY_mm: 0.5; SizeZ_mm: 0.6; Value2: 0.063W; AEC Qualified: Y; VDC_V: 50V; AEC Category: Q200; AEC Grade: 0
R96 = CMP-0026822-3: RES, 0, 5%, 0.063 W, AEC-Q200 Grade 0, 0402; Manufacturer: Vishay-Dale; Power_W: 63mW; TempCo: 200 ppm/C; Value_Code: 0000; Value: 0; EIA_Code: E24; SizeX_mm: 1; SizeY_mm: 0.5; SizeZ_mm: 0.6; Value2: 0.063W; AEC Qualified: Y; VDC_V: 50V; AEC Category: Q200
U3 = CMP-0001411-1: Ethernet PHY 10BASE-Te/00BASE-TX 10/100 Mbps 160mW 1.8V/3.3V 2-Pin VQFN Industrial; Manufacturer: Texas Instruments; SizeZ_mm: 1mm; AEC Qualified: No; Data Rate: 100Mbits/s; Max Supply Voltage: 3.6V; Min Supply Voltage: 1.62V; Number Of Channels: 1; Simplex Duplex: Full-Duplex; Standoff Height: 0mm; TaMax_C: +85°C; TaMin_C: -40°C
U6 = CMP-0073613-3: 4-Channel Ultra-Low-Capacitance IEC ESD Protection Diode, DQA0010A (USON-10); Alternate Manufacturer: Texas Instruments; Green_Lifecycle: Active; SizeAreaWB_mm2: 7.0; Green_REACh: Passed; SizeZ_mm: 0.55; SizeX_mm: 1.0; SizeY_mm: 2.5; CompType: IC; AEC Category: Q200; AEC Qualified: N
U7 = CMP-0051777-2: Dual Inverter Buffer/Driver with Open-Drain Output, DBV0006A, LARGE T&R; Manufacturer: Texas Instruments; Technology Family: LVC; Input Type: CMOS/TTL; Output Drive (IOL/IOH)(Max)(mA): 32/-32; tpd @ Nom Voltage(Max)(ns): 8.2,4.4,3.9,3.4; Voltage(Nom)(V): 1.8,2.5,3.3,5; 3-State Output: No; Rating: Catalog; Sub-Family: Inverting Buffer/Driver; Logic: Inverting; VCC(Min)(V): 1.65; F @ Nom Voltage(Max)(Mhz): 150; Output Type: CMOS; ICC @ Nom Voltage(Max)(mA): 0.01; Bits(#): 2; VCC(Max)(V): 5.5
U8 = CMP-0082059-1: 16 Kb I2C EEPROM Serial, SOIC-8; Manufacturer: ON Semiconductor; SizeArea_mm2: 29.351; SizeAreaWB_mm2: 55.131; SizeY_mm: 4.9; SizeZ_mm: 1.75; SizeX_mm: 5.99

## Sheet MCU134A_EtherCAT_PHY_1.SchDoc
size 431 x 279 mm; SheetNumber: 8; SheetTotal: 13
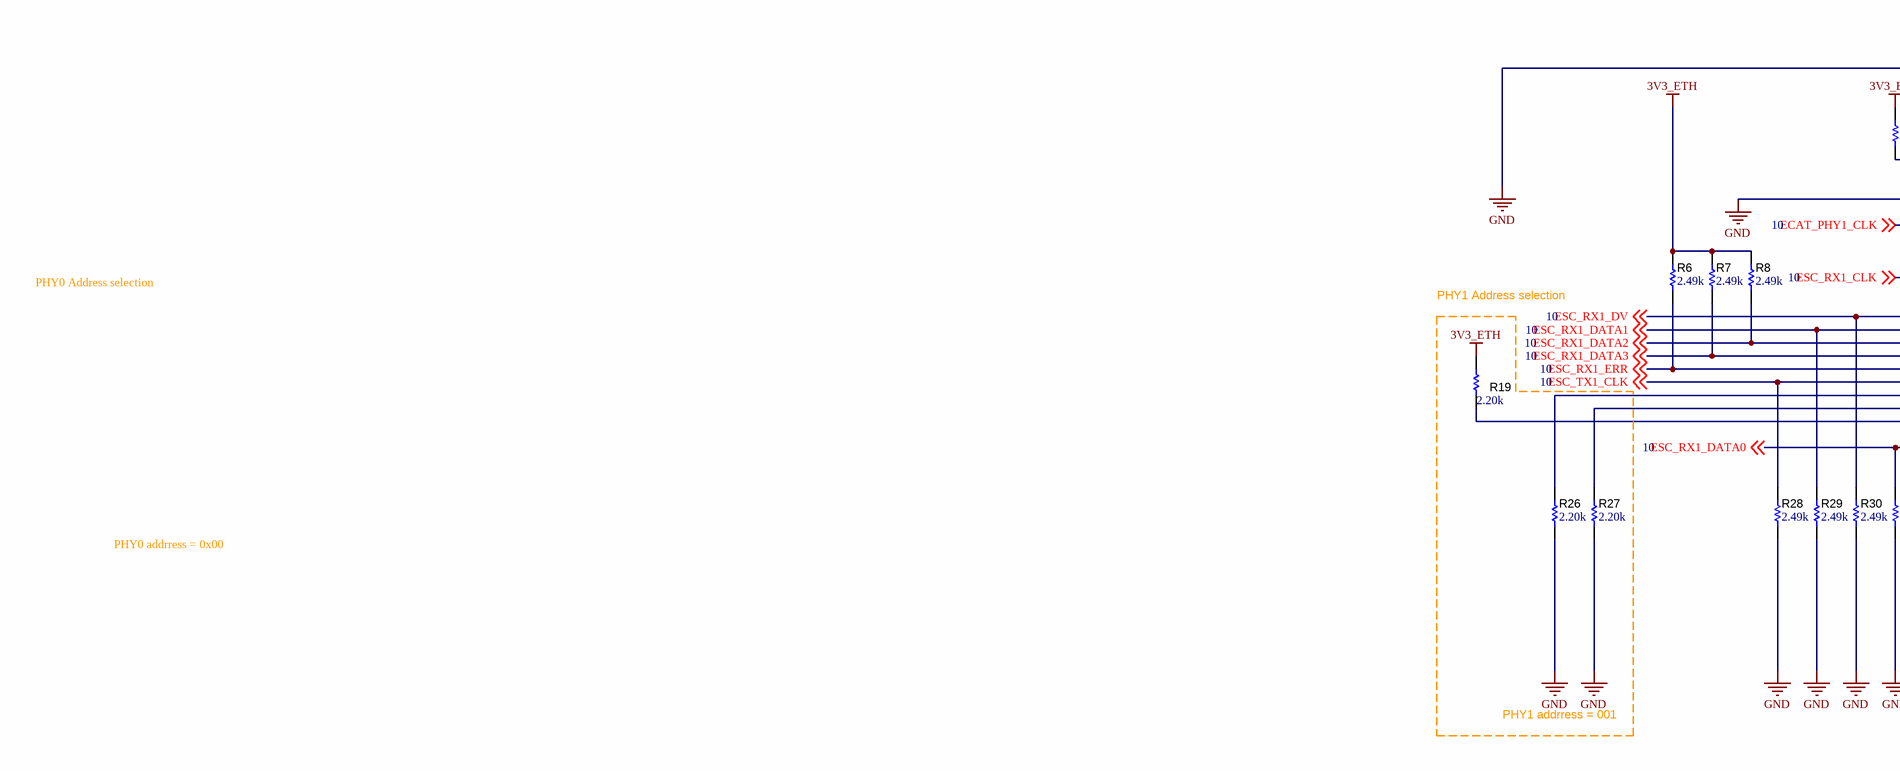
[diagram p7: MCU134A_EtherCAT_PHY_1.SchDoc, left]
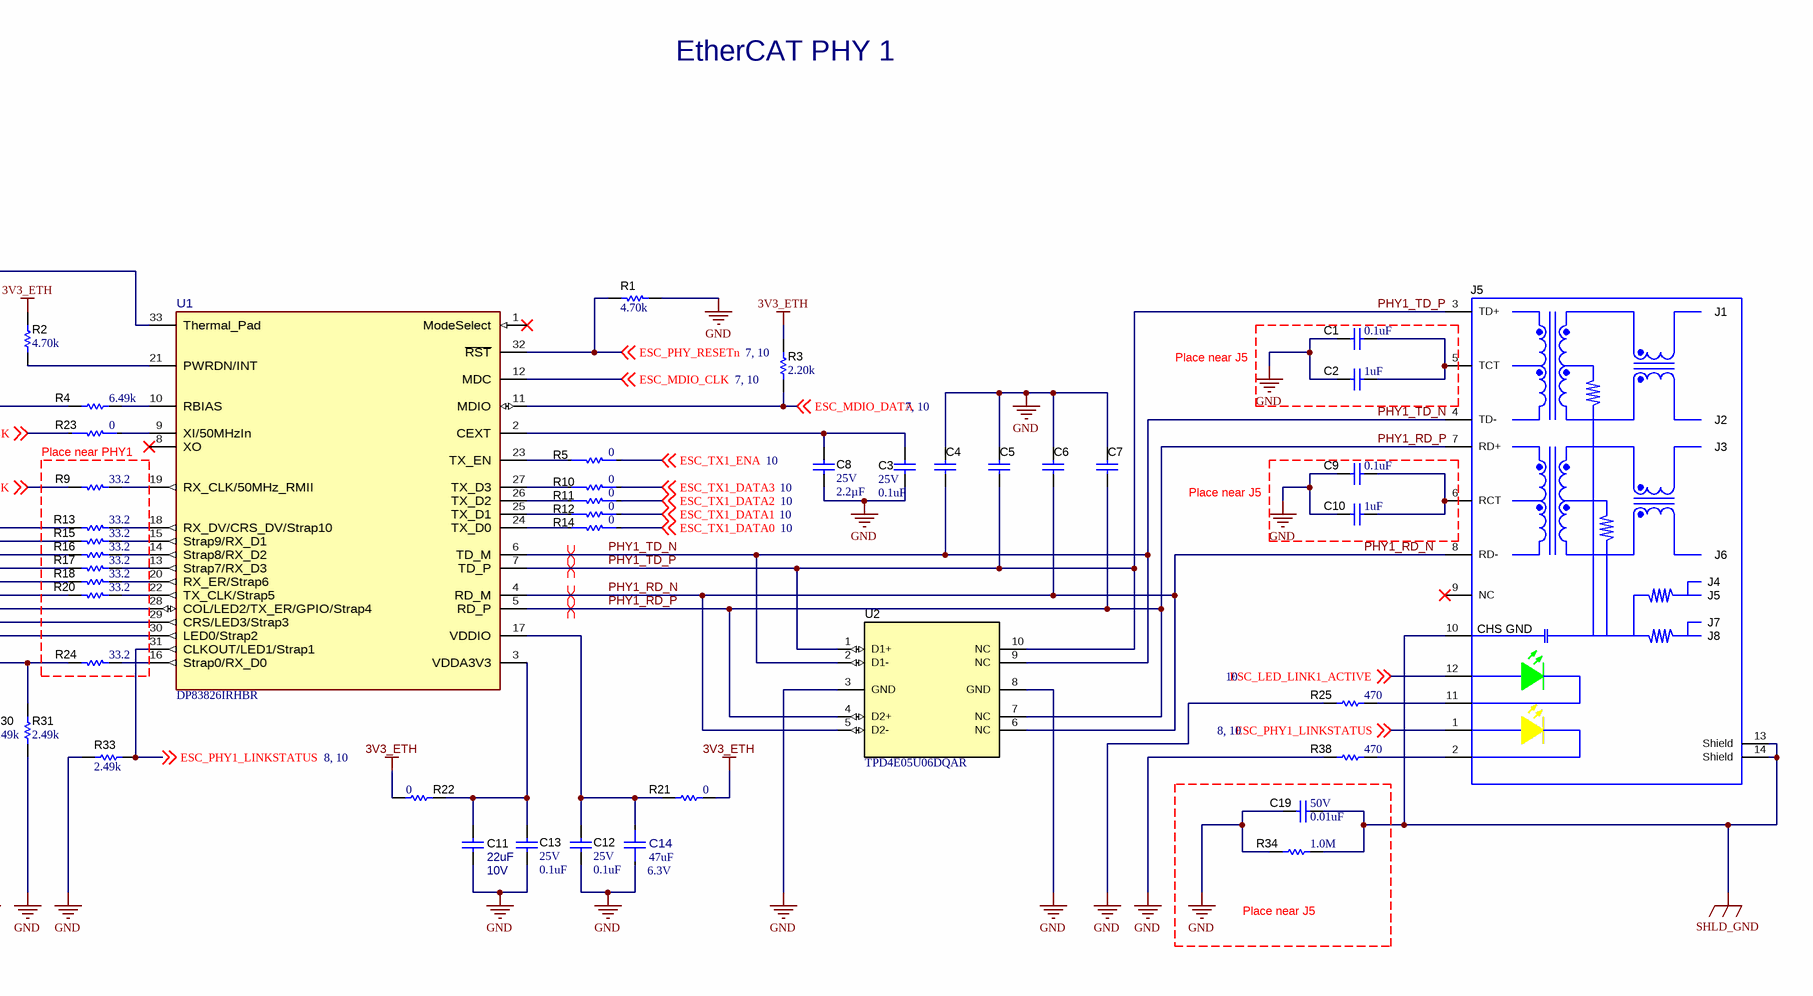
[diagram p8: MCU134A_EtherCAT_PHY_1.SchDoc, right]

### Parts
C1  ValueDisplayed: 0.1uF  [0402]  (hidden comment: GRM155R71E104KE14D)
C2  value 1uF  [0402]  (hidden comment: GRM155R61E105KE11D)
C3  VDC_V: 25V  ValueDisplayed: 0.1uF  [0402]  (hidden comment: GRM155R71E104KE14D)
C4  GJM1555C1H4R7BB01D  [0402]  (value not drawn)
C5  GJM1555C1H4R7BB01D  [0402]  (value not drawn)
C6  GJM1555C1H4R7BB01D  [0402]  (value not drawn)
C7  GJM1555C1H4R7BB01D  [0402]  (value not drawn)
C8  VDC_V: 25V  ValueDisplayed: 2.2µF  [0402]  (hidden comment: GRM155R61E225ME15D)
C9  ValueDisplayed: 0.1uF  [0402]  (hidden comment: GRM155R71E104KE14D)
C10  value 1uF  [0402]  (hidden comment: GRM155R61E105KE11D)
C11  Value2: 10V  ValueDisplayed: 22uF  [0603]  (hidden comment: GRM188R61A226ME15D)
C12  VDC_V: 25V  ValueDisplayed: 0.1uF  [0402]  (hidden comment: GRM155R71E104KE14D)
C13  VDC_V: 25V  ValueDisplayed: 0.1uF  [0402]  (hidden comment: GRM155R71E104KE14D)
C14  VDC_V: 6.3V  ValueDisplayed: 47uF  [FP-GRM188R60J476ME01D_0603-MFG]  (hidden comment: GRM188R60J476ME01D)
C19  VDC_V: 50V  ValueDisplayed: 0.01uF  [0805_HV]  (hidden comment: GRM2195C1H103JA01D)
J5  7498010210A  [Wurth_7498010210A]  (value not drawn)
R1  ValueDisplayed: 4.70k  [0402]  (hidden comment: CRG0402F4K7)
R2  ValueDisplayed: 4.70k  [0402]  (hidden comment: CRG0402F4K7)
R3  ValueDisplayed: 2.20k  [0402]  (hidden comment: CRCW04022K20FKED)
R4  ValueDisplayed: 6.49k  [0402]  (hidden comment: CRCW04026K49FKED)
R5  value 0  [FP-CRCW04020000Z0EDHP_0402-MFG]  (hidden comment: CRCW04020000Z0EDHP)
R6  ValueDisplayed: 2.49k  [0402]  (hidden comment: CRCW04022K49FKED)
R7  ValueDisplayed: 2.49k  [0402]  (hidden comment: CRCW04022K49FKED)
R8  ValueDisplayed: 2.49k  [0402]  (hidden comment: CRCW04022K49FKED)
R9  ValueDisplayed: 33.2  [0402]  (hidden comment: CRCW040233R2FKED)
R10  value 0  [FP-CRCW04020000Z0EDHP_0402-MFG]  (hidden comment: CRCW04020000Z0EDHP)
R11  value 0  [FP-CRCW04020000Z0EDHP_0402-MFG]  (hidden comment: CRCW04020000Z0EDHP)
R12  value 0  [FP-CRCW04020000Z0EDHP_0402-MFG]  (hidden comment: CRCW04020000Z0EDHP)
R13  ValueDisplayed: 33.2  [0402]  (hidden comment: CRCW040233R2FKED)
R14  value 0  [FP-CRCW04020000Z0EDHP_0402-MFG]  (hidden comment: CRCW04020000Z0EDHP)
R15  ValueDisplayed: 33.2  [0402]  (hidden comment: CRCW040233R2FKED)
R16  ValueDisplayed: 33.2  [0402]  (hidden comment: CRCW040233R2FKED)
R17  ValueDisplayed: 33.2  [0402]  (hidden comment: CRCW040233R2FKED)
R18  ValueDisplayed: 33.2  [0402]  (hidden comment: CRCW040233R2FKED)
R19  ValueDisplayed: 2.20k  [0402]  (hidden comment: CRCW04022K20FKED)
R20  ValueDisplayed: 33.2  [0402]  (hidden comment: CRCW040233R2FKED)
R21  ValueDisplayed: 0  [0603]  (hidden comment: ERJ-3GEY0R00V)
R22  ValueDisplayed: 0  [0603]  (hidden comment: ERJ-3GEY0R00V)
R23  value 0  [FP-CRCW04020000Z0EDHP_0402-MFG]  (hidden comment: CRCW04020000Z0EDHP)
R24  ValueDisplayed: 33.2  [0402]  (hidden comment: CRCW040233R2FKED)
R25  ValueDisplayed: 470  [0603]  (hidden comment: CRCW0603470RJNEA)
R26  ValueDisplayed: 2.20k  [0402]  (hidden comment: CRCW04022K20FKED)
R27  ValueDisplayed: 2.20k  [0402]  (hidden comment: CRCW04022K20FKED)
R28  ValueDisplayed: 2.49k  [0402]  (hidden comment: CRCW04022K49FKED)
R29  ValueDisplayed: 2.49k  [0402]  (hidden comment: CRCW04022K49FKED)
R30  ValueDisplayed: 2.49k  [0402]  (hidden comment: CRCW04022K49FKED)
R31  ValueDisplayed: 2.49k  [0402]  (hidden comment: CRCW04022K49FKED)
R33  ValueDisplayed: 2.49k  [0402]  (hidden comment: CRCW04022K49FKED)
R34  ValueDisplayed: 1.0M  [0805_HV]  (hidden comment: ERJ-6GEYJ105V)
R38  ValueDisplayed: 470  [0603]  (hidden comment: CRCW0603470RJNEA)
U1  DP83826IRHBR  [RHB0032M-MFG]
U2  TPD4E05U06DQAR  [DQA0010A]

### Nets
3V3_ETH: R2.1 R3.2 R6.2 R7.2 R8.2 R19.2 R21.2 R22.1
GND: C1.2 C2.2 C3.2 C4.1 C5.1 C6.1 C7.1 C8.2 C9.2 C10.2 C11.2 C12.2 C13.2 C14.1 C19.2 R1.2 R4.1 R25.1 R26.1 R27.1 R28.1 R29.1 R30.1 R31.1 R33.1 R34.1 R38.1 U1.33(Thermal_Pad) U2.3(GND) U2.8(GND)
SHLD_GND: C19.1 J5.10(CHS_GND) J5.13(Shield) J5.14(Shield) R34.2
ECAT_PHY1_CLK: R23.1 ; off-sheet ECAT_PHY1_CLK
ESC_LED_LINK1_ACTIVE: J5.12(LEFT_LED_ANODE) ; off-sheet ESC_LED_LINK1_ACTIVE
ESC_MDIO_CLK: U1.12(MDC) ; off-sheet ESC_MDIO_CLK
ESC_MDIO_DATA: R3.1 U1.11(MDIO) ; off-sheet ESC_MDIO_DATA
ESC_PHY1_LINKSTATUS: J5.1(RIGHT_LED_ANODE) R33.2 U1.31(CLKOUT/LED1/Strap1) ; off-sheet ESC_PHY1_LINKSTATUS
ESC_PHY_RESETn: R1.1 U1.32(~{RST}) ; off-sheet ESC_PHY_RESETn
ESC_RX1_CLK: R9.1 ; off-sheet ESC_RX1_CLK
ESC_RX1_DATA0: R24.1 R31.2 ; off-sheet ESC_RX1_DATA0
ESC_RX1_DATA1: R15.1 R29.2 ; off-sheet ESC_RX1_DATA1
ESC_RX1_DATA2: R8.1 R16.1 ; off-sheet ESC_RX1_DATA2
ESC_RX1_DATA3: R7.1 R17.1 ; off-sheet ESC_RX1_DATA3
ESC_RX1_DV: R13.1 R30.2 ; off-sheet ESC_RX1_DV
ESC_RX1_ERR: R6.1 R18.1 ; off-sheet ESC_RX1_ERR
ESC_TX1_CLK: R20.1 R28.2 ; off-sheet ESC_TX1_CLK
ESC_TX1_DATA0: R14.2 ; off-sheet ESC_TX1_DATA0
ESC_TX1_DATA1: R12.2 ; off-sheet ESC_TX1_DATA1
ESC_TX1_DATA2: R11.2 ; off-sheet ESC_TX1_DATA2
ESC_TX1_DATA3: R10.2 ; off-sheet ESC_TX1_DATA3
ESC_TX1_ENA: R5.2 ; off-sheet ESC_TX1_ENA
PHY1_RD_N: C6.2 J5.8(RD-) U1.4(RD_M) U2.5(D2-) U2.6(NC)
PHY1_RD_P: C7.2 J5.7(RD+) U1.5(RD_P) U2.4(D2+) U2.7(NC)
PHY1_TD_N: C4.2 J5.4(TD-) U1.6(TD_M) U2.2(D1-) U2.9(NC)
PHY1_TD_P: C5.2 J5.3(TD+) U1.7(TD_P) U2.1(D1+) U2.10(NC)
NetC1_1: C1.1 C2.1 J5.5(TCT)
NetC3_1: C3.1 C8.1 U1.2(CEXT)
NetC9_1: C9.1 C10.1 J5.6(RCT)
NetC11_1: C11.1 C13.1 R22.2 U1.3(VDDA3V3)
NetC12_1: C12.1 C14.2 R21.1 U1.17(VDDIO)
NetJ5_2: J5.2(RIGHT_LED_CATHODE) R38.2
NetJ5_11: J5.11(LEFT_LED_CATHODE) R25.2
NetR2_2: R2.2 U1.21(PWRDN/INT)
NetR4_2: R4.2 U1.10(RBIAS)
NetR5_1: R5.1 U1.23(TX_EN)
NetR9_2: R9.2 U1.19(RX_CLK/50MHz_RMII)
NetR10_1: R10.1 U1.27(TX_D3)
NetR11_1: R11.1 U1.26(TX_D2)
NetR12_1: R12.1 U1.25(TX_D1)
NetR13_2: R13.2 U1.18(RX_DV/CRS_DV/Strap10)
NetR14_1: R14.1 U1.24(TX_D0)
NetR15_2: R15.2 U1.15(Strap9/RX_D1)
NetR16_2: R16.2 U1.14(Strap8/RX_D2)
NetR17_2: R17.2 U1.13(Strap7/RX_D3)
NetR18_2: R18.2 U1.20(RX_ER/Strap6)
NetR19_1: R19.1 U1.30(LED0/Strap2)
NetR20_2: R20.2 U1.22(TX_CLK/Strap5)
NetR23_2: R23.2 U1.9(XI/50MHzIn)
NetR24_2: R24.2 U1.16(Strap0/RX_D0)
NetR26_2: R26.2 U1.28(COL/LED2/TX_ER/GPIO/Strap4)
NetR27_2: R27.2 U1.29(CRS/LED3/Strap3)

Not connected (* = marked no-connect by the designer): J5 9(NC)*; U1 1(ModeSelect)* 8(XO)*

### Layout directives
differential pair: PHY1_RD_N, PHY1_RD_P, PHY1_TD_N, PHY1_TD_P

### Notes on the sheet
- EtherCAT PHY 1
- Place near J5
- (near R23) Place near PHY1
- PHY0 Address selection
- PHY1 Address selection
- PHY0 addrress = 0x00
- PHY1 addrress = 001

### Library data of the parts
C1 C9 = CMP-0006659-2: as C41 on sheet MCU134A_EtherCAT_PHY_0
C2 C10 = CMP-0086061-1: as C42 on sheet MCU134A_EtherCAT_PHY_0
C3 C12 C13 = CMP-0006659-2: as C15 on sheet MCU134A_EtherCAT_PHY_0
C4-C7 = CMP-0006367-2: as C43 on sheet MCU134A_EtherCAT_PHY_0
C8 = CMP-0081010-1: as C47 on sheet MCU134A_EtherCAT_PHY_0
C11 = CMP-0007324-5: as C16 on sheet MCU134A_EtherCAT_PHY_0
C14 = CMP-0120208-1: as C17 on sheet MCU134A_EtherCAT_PHY_0
C19 = CMP-0008156-2: as C59 on sheet MCU134A_EtherCAT_PHY_0
J5 = CMP-0086350-1: as J11 on sheet MCU134A_EtherCAT_PHY_0
R1 R2 = CMP-0026631-1: as R56 on sheet MCU134A_EtherCAT_PHY_0
R3 R19 R26 R27 = CMP-0026231-2: as R58 on sheet MCU134A_EtherCAT_PHY_0
R4 = CMP-0026515-2: as R59 on sheet MCU134A_EtherCAT_PHY_0
R5 R10-R12 R14 R23 = CMP-0001606-1: as R32 on sheet MCU134A_EtherCAT_PHY_0
R6-R8 R28-R31 R33 = CMP-0026237-2: as R61 on sheet MCU134A_EtherCAT_PHY_0
R9 R13 R15-R18 R20 R24 = CMP-0026299-2: as R64 on sheet MCU134A_EtherCAT_PHY_0
R21 R22 = CMP-0025874-4: as R35 on sheet MCU134A_EtherCAT_PHY_0
R25 R38 = CMP-0025813-4: as R79 on sheet MCU134A_EtherCAT_PHY_0
R34 = CMP-0020623-3: as R89 on sheet MCU134A_EtherCAT_PHY_0
U1 = CMP-0001411-1: as U3 on sheet MCU134A_EtherCAT_PHY_0
U2 = CMP-0073613-3: as U6 on sheet MCU134A_EtherCAT_PHY_0

## Sheet MCU134A_High_Density_Conn1_2.SchDoc
size 431 x 279 mm; SheetNumber: 9; SheetTotal: 13
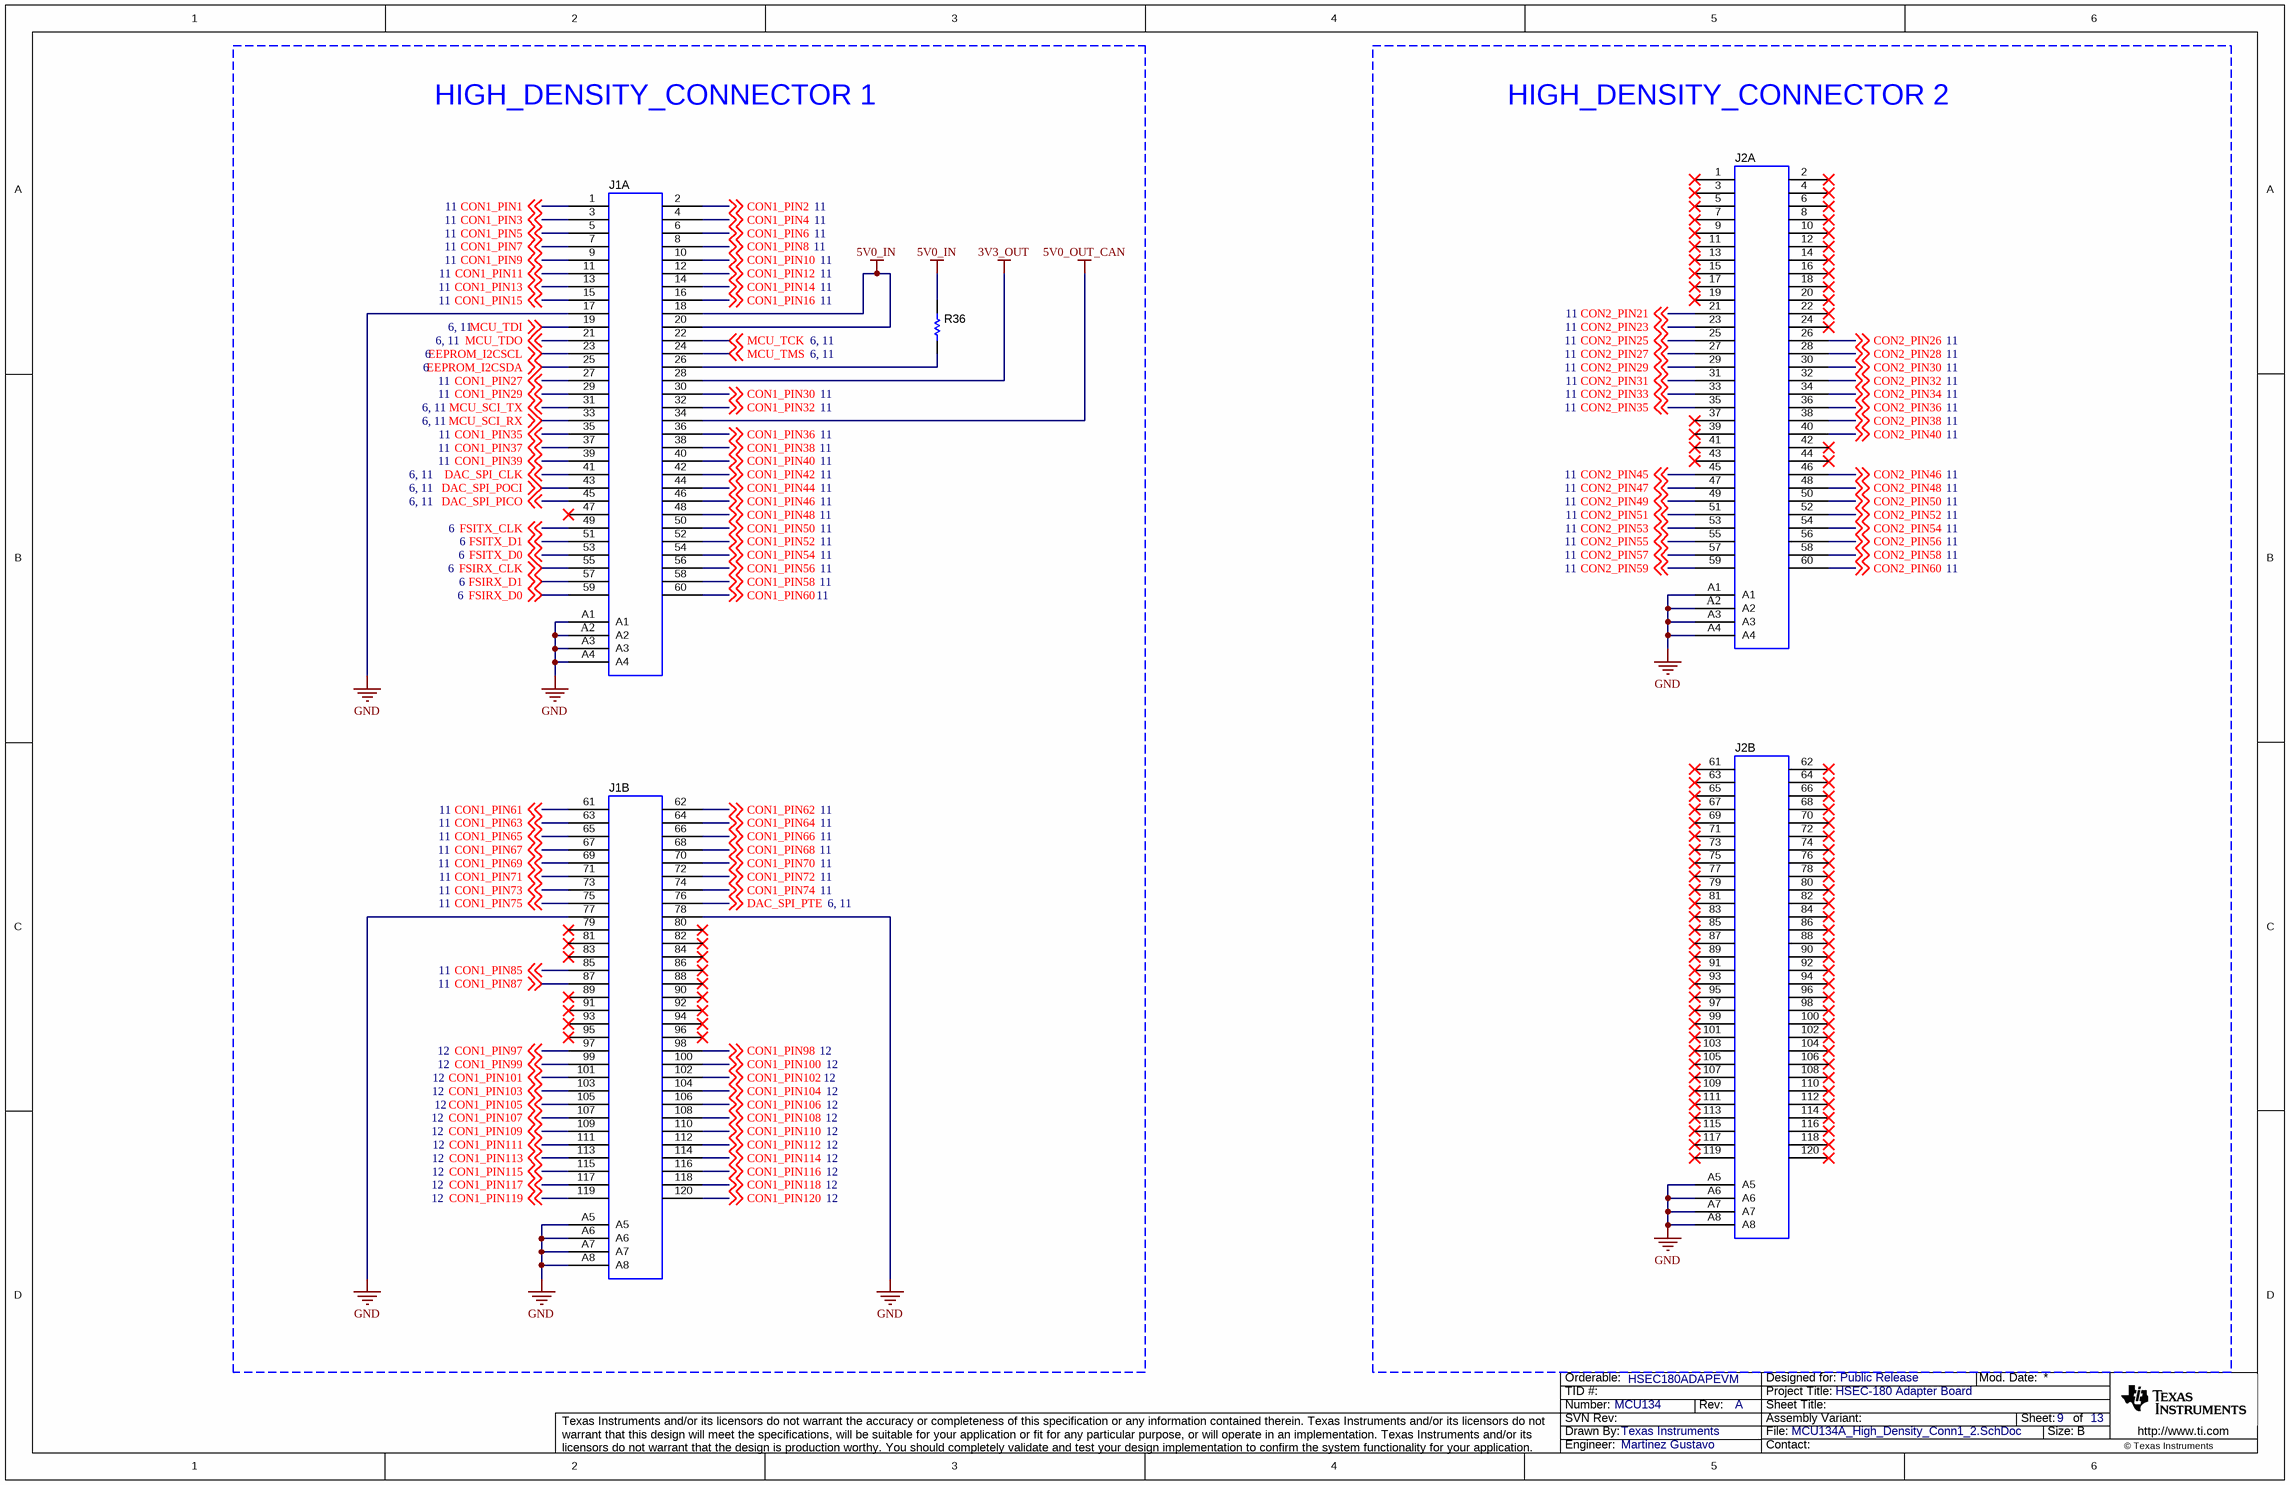
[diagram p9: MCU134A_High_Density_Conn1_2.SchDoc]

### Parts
J1  QTH-060-01-L-D-A  [SAMTEC_QTH-060-01-L-D-A]  (value not drawn)  (parts A,B of 2)
J2  QTH-060-01-L-D-A  [SAMTEC_QTH-060-01-L-D-A]  (value not drawn)  (parts A,B of 2)
R36  AC0402FR-0710KL  [0402]  (value not drawn)

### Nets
3V3_OUT: J1.28
5V0_IN: J1.18 J1.20 R36.2
5V0_OUT_CAN: J1.34
GND: J1.17 J1.77 J1.78 J1.A1 J1.A2 J1.A3 J1.A4 J1.A5 J1.A6 J1.A7 J1.A8 J2.A1 J2.A2 J2.A3 J2.A4 J2.A5 J2.A6 J2.A7 J2.A8
CON1_PIN1: J1.1 ; off-sheet CON1_PIN1
CON1_PIN2: J1.2 ; off-sheet CON1_PIN2
CON1_PIN3: J1.3 ; off-sheet CON1_PIN3
CON1_PIN4: J1.4 ; off-sheet CON1_PIN4
CON1_PIN5: J1.5 ; off-sheet CON1_PIN5
CON1_PIN6: J1.6 ; off-sheet CON1_PIN6
CON1_PIN7: J1.7 ; off-sheet CON1_PIN7
CON1_PIN8: J1.8 ; off-sheet CON1_PIN8
CON1_PIN9: J1.9 ; off-sheet CON1_PIN9
CON1_PIN10: J1.10 ; off-sheet CON1_PIN10
CON1_PIN11: J1.11 ; off-sheet CON1_PIN11
CON1_PIN12: J1.12 ; off-sheet CON1_PIN12
CON1_PIN13: J1.13 ; off-sheet CON1_PIN13
CON1_PIN14: J1.14 ; off-sheet CON1_PIN14
CON1_PIN15: J1.15 ; off-sheet CON1_PIN15
CON1_PIN16: J1.16 ; off-sheet CON1_PIN16
CON1_PIN27: J1.27 ; off-sheet CON1_PIN27
CON1_PIN29: J1.29 ; off-sheet CON1_PIN29
CON1_PIN30: J1.30 ; off-sheet CON1_PIN30
CON1_PIN32: J1.32 ; off-sheet CON1_PIN32
CON1_PIN35: J1.35 ; off-sheet CON1_PIN35
CON1_PIN36: J1.36 ; off-sheet CON1_PIN36
CON1_PIN37: J1.37 ; off-sheet CON1_PIN37
CON1_PIN38: J1.38 ; off-sheet CON1_PIN38
CON1_PIN39: J1.39 ; off-sheet CON1_PIN39
CON1_PIN40: J1.40 ; off-sheet CON1_PIN40
CON1_PIN42: J1.42 ; off-sheet CON1_PIN42
CON1_PIN44: J1.44 ; off-sheet CON1_PIN44
CON1_PIN46: J1.46 ; off-sheet CON1_PIN46
CON1_PIN48: J1.48 ; off-sheet CON1_PIN48
CON1_PIN50: J1.50 ; off-sheet CON1_PIN50
CON1_PIN52: J1.52 ; off-sheet CON1_PIN52
CON1_PIN54: J1.54 ; off-sheet CON1_PIN54
CON1_PIN56: J1.56 ; off-sheet CON1_PIN56
CON1_PIN58: J1.58 ; off-sheet CON1_PIN58
CON1_PIN60: J1.60 ; off-sheet CON1_PIN60
CON1_PIN61: J1.61 ; off-sheet CON1_PIN61
CON1_PIN62: J1.62 ; off-sheet CON1_PIN62
CON1_PIN63: J1.63 ; off-sheet CON1_PIN63
CON1_PIN64: J1.64 ; off-sheet CON1_PIN64
CON1_PIN65: J1.65 ; off-sheet CON1_PIN65
CON1_PIN66: J1.66 ; off-sheet CON1_PIN66
CON1_PIN67: J1.67 ; off-sheet CON1_PIN67
CON1_PIN68: J1.68 ; off-sheet CON1_PIN68
CON1_PIN69: J1.69 ; off-sheet CON1_PIN69
CON1_PIN70: J1.70 ; off-sheet CON1_PIN70
CON1_PIN71: J1.71 ; off-sheet CON1_PIN71
CON1_PIN72: J1.72 ; off-sheet CON1_PIN72
CON1_PIN73: J1.73 ; off-sheet CON1_PIN73
CON1_PIN74: J1.74 ; off-sheet CON1_PIN74
CON1_PIN75: J1.75 ; off-sheet CON1_PIN75
CON1_PIN85: J1.85 ; off-sheet CON1_PIN85
CON1_PIN87: J1.87 ; off-sheet CON1_PIN87
CON1_PIN97: J1.97 ; off-sheet CON1_PIN97
CON1_PIN98: J1.98 ; off-sheet CON1_PIN98
CON1_PIN99: J1.99 ; off-sheet CON1_PIN99
CON1_PIN100: J1.100 ; off-sheet CON1_PIN100
CON1_PIN101: J1.101 ; off-sheet CON1_PIN101
CON1_PIN102: J1.102 ; off-sheet CON1_PIN102
CON1_PIN103: J1.103 ; off-sheet CON1_PIN103
CON1_PIN104: J1.104 ; off-sheet CON1_PIN104
CON1_PIN105: J1.105 ; off-sheet CON1_PIN105
CON1_PIN106: J1.106 ; off-sheet CON1_PIN106
CON1_PIN107: J1.107 ; off-sheet CON1_PIN107
CON1_PIN108: J1.108 ; off-sheet CON1_PIN108
CON1_PIN109: J1.109 ; off-sheet CON1_PIN109
CON1_PIN110: J1.110 ; off-sheet CON1_PIN110
CON1_PIN111: J1.111 ; off-sheet CON1_PIN111
CON1_PIN112: J1.112 ; off-sheet CON1_PIN112
CON1_PIN113: J1.113 ; off-sheet CON1_PIN113
CON1_PIN114: J1.114 ; off-sheet CON1_PIN114
CON1_PIN115: J1.115 ; off-sheet CON1_PIN115
CON1_PIN116: J1.116 ; off-sheet CON1_PIN116
CON1_PIN117: J1.117 ; off-sheet CON1_PIN117
CON1_PIN118: J1.118 ; off-sheet CON1_PIN118
CON1_PIN119: J1.119 ; off-sheet CON1_PIN119
CON1_PIN120: J1.120 ; off-sheet CON1_PIN120
CON2_PIN21: J2.21 ; off-sheet CON2_PIN21
CON2_PIN23: J2.23 ; off-sheet CON2_PIN23
CON2_PIN25: J2.25 ; off-sheet CON2_PIN25
CON2_PIN26: J2.26 ; off-sheet CON2_PIN26
CON2_PIN27: J2.27 ; off-sheet CON2_PIN27
CON2_PIN28: J2.28 ; off-sheet CON2_PIN28
CON2_PIN29: J2.29 ; off-sheet CON2_PIN29
CON2_PIN30: J2.30 ; off-sheet CON2_PIN30
CON2_PIN31: J2.31 ; off-sheet CON2_PIN31
CON2_PIN32: J2.32 ; off-sheet CON2_PIN32
CON2_PIN33: J2.33 ; off-sheet CON2_PIN33
CON2_PIN34: J2.34 ; off-sheet CON2_PIN34
CON2_PIN35: J2.35 ; off-sheet CON2_PIN35
CON2_PIN36: J2.36 ; off-sheet CON2_PIN36
CON2_PIN38: J2.38 ; off-sheet CON2_PIN38
CON2_PIN40: J2.40 ; off-sheet CON2_PIN40
CON2_PIN45: J2.45 ; off-sheet CON2_PIN45
CON2_PIN46: J2.46 ; off-sheet CON2_PIN46
CON2_PIN47: J2.47 ; off-sheet CON2_PIN47
CON2_PIN48: J2.48 ; off-sheet CON2_PIN48
CON2_PIN49: J2.49 ; off-sheet CON2_PIN49
CON2_PIN50: J2.50 ; off-sheet CON2_PIN50
CON2_PIN51: J2.51 ; off-sheet CON2_PIN51
CON2_PIN52: J2.52 ; off-sheet CON2_PIN52
CON2_PIN53: J2.53 ; off-sheet CON2_PIN53
CON2_PIN54: J2.54 ; off-sheet CON2_PIN54
CON2_PIN55: J2.55 ; off-sheet CON2_PIN55
CON2_PIN56: J2.56 ; off-sheet CON2_PIN56
CON2_PIN57: J2.57 ; off-sheet CON2_PIN57
CON2_PIN58: J2.58 ; off-sheet CON2_PIN58
CON2_PIN59: J2.59 ; off-sheet CON2_PIN59
CON2_PIN60: J2.60 ; off-sheet CON2_PIN60
DAC_SPI_CLK: J1.41 ; off-sheet DAC_SPI_CLK
DAC_SPI_PICO: J1.45 ; off-sheet DAC_SPI_PICO
DAC_SPI_POCI: J1.43 ; off-sheet DAC_SPI_POCI
DAC_SPI_PTE: J1.76 ; off-sheet DAC_SPI_PTE
EEPROM_I2CSCL: J1.23 ; off-sheet EEPROM_I2CSCL
EEPROM_I2CSDA: J1.25 ; off-sheet EEPROM_I2CSDA
FSIRX_CLK: J1.55 ; off-sheet FSIRX_CLK
FSIRX_D0: J1.59 ; off-sheet FSIRX_D0
FSIRX_D1: J1.57 ; off-sheet FSIRX_D1
FSITX_CLK: J1.49 ; off-sheet FSITX_CLK
FSITX_D0: J1.53 ; off-sheet FSITX_D0
FSITX_D1: J1.51 ; off-sheet FSITX_D1
MCU_SCI_RX: J1.33 ; off-sheet MCU_SCI_RX
MCU_SCI_TX: J1.31 ; off-sheet MCU_SCI_TX
MCU_TCK: J1.22 ; off-sheet MCU_TCK
MCU_TDI: J1.19 ; off-sheet MCU_TDI
MCU_TDO: J1.21 ; off-sheet MCU_TDO
MCU_TMS: J1.24 ; off-sheet MCU_TMS
NetJ1_26: J1.26 R36.1

Not connected (* = marked no-connect by the designer): J1 47* 79* 80* 81* 82* 83* 84* 86* 88* 89* 90* 91* 92* 93* 94* 95* 96*; J2 1* 2* 3* 4* 5* 6* 7* 8* 9* 10* 11* 12* 13* 14* 15* 16* 17* 18* 19* 20* 22* 24* 37* 39* 41* 42* 43* 44* 61* 62* 63* 64* 65* 66* 67* 68* 69* 70* 71* 72* 73* 74* 75* 76* 77* 78* 79* 80* 81* 82* 83* 84* 85* 86* 87* 88* 89* 90* 91* 92* 93* 94* 95* 96* 97* 98* 99* 100* 101* 102* 103* 104* 105* 106* 107* 108* 109* 110* 111* 112* 113* 114* 115* 116* 117* 118* 119* 120*

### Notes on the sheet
- HIGH_DENSITY_CONNECTOR 1
- HIGH_DENSITY_CONNECTOR 2

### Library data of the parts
J1 J2 = CMP-0056023-2: Socket, 0.5MM, 60x2, Gold, SMT; Manufacturer: Samtec; Green_Lifecycle: Not Set; Green_REACh: Incomplete
R36 = CMP-0077731-1: RES, 10.0 k, 1%, 0.063 W, AEC-Q200 Grade 0, 0402; Manufacturer: Yageo America; Power_W: 63mW; TempCo: 100 ppm/C; Value_Code: 10k0; U/M: EA; Value: 10.0k; EIA_Code: E96; Res_ohm: 10k; SizeX_mm: 1.0; SizeY_mm: 0.5; SizeZ_mm: 0.6; Value2: 0.063W; AEC Qualified: Y; VDC_V: 50V; AEC Grade: 0; AEC Category: Q200

## Sheet MCU134A_High_Density_Conn3_4.SchDoc
size 431 x 279 mm; SheetNumber: 10; SheetTotal: 13
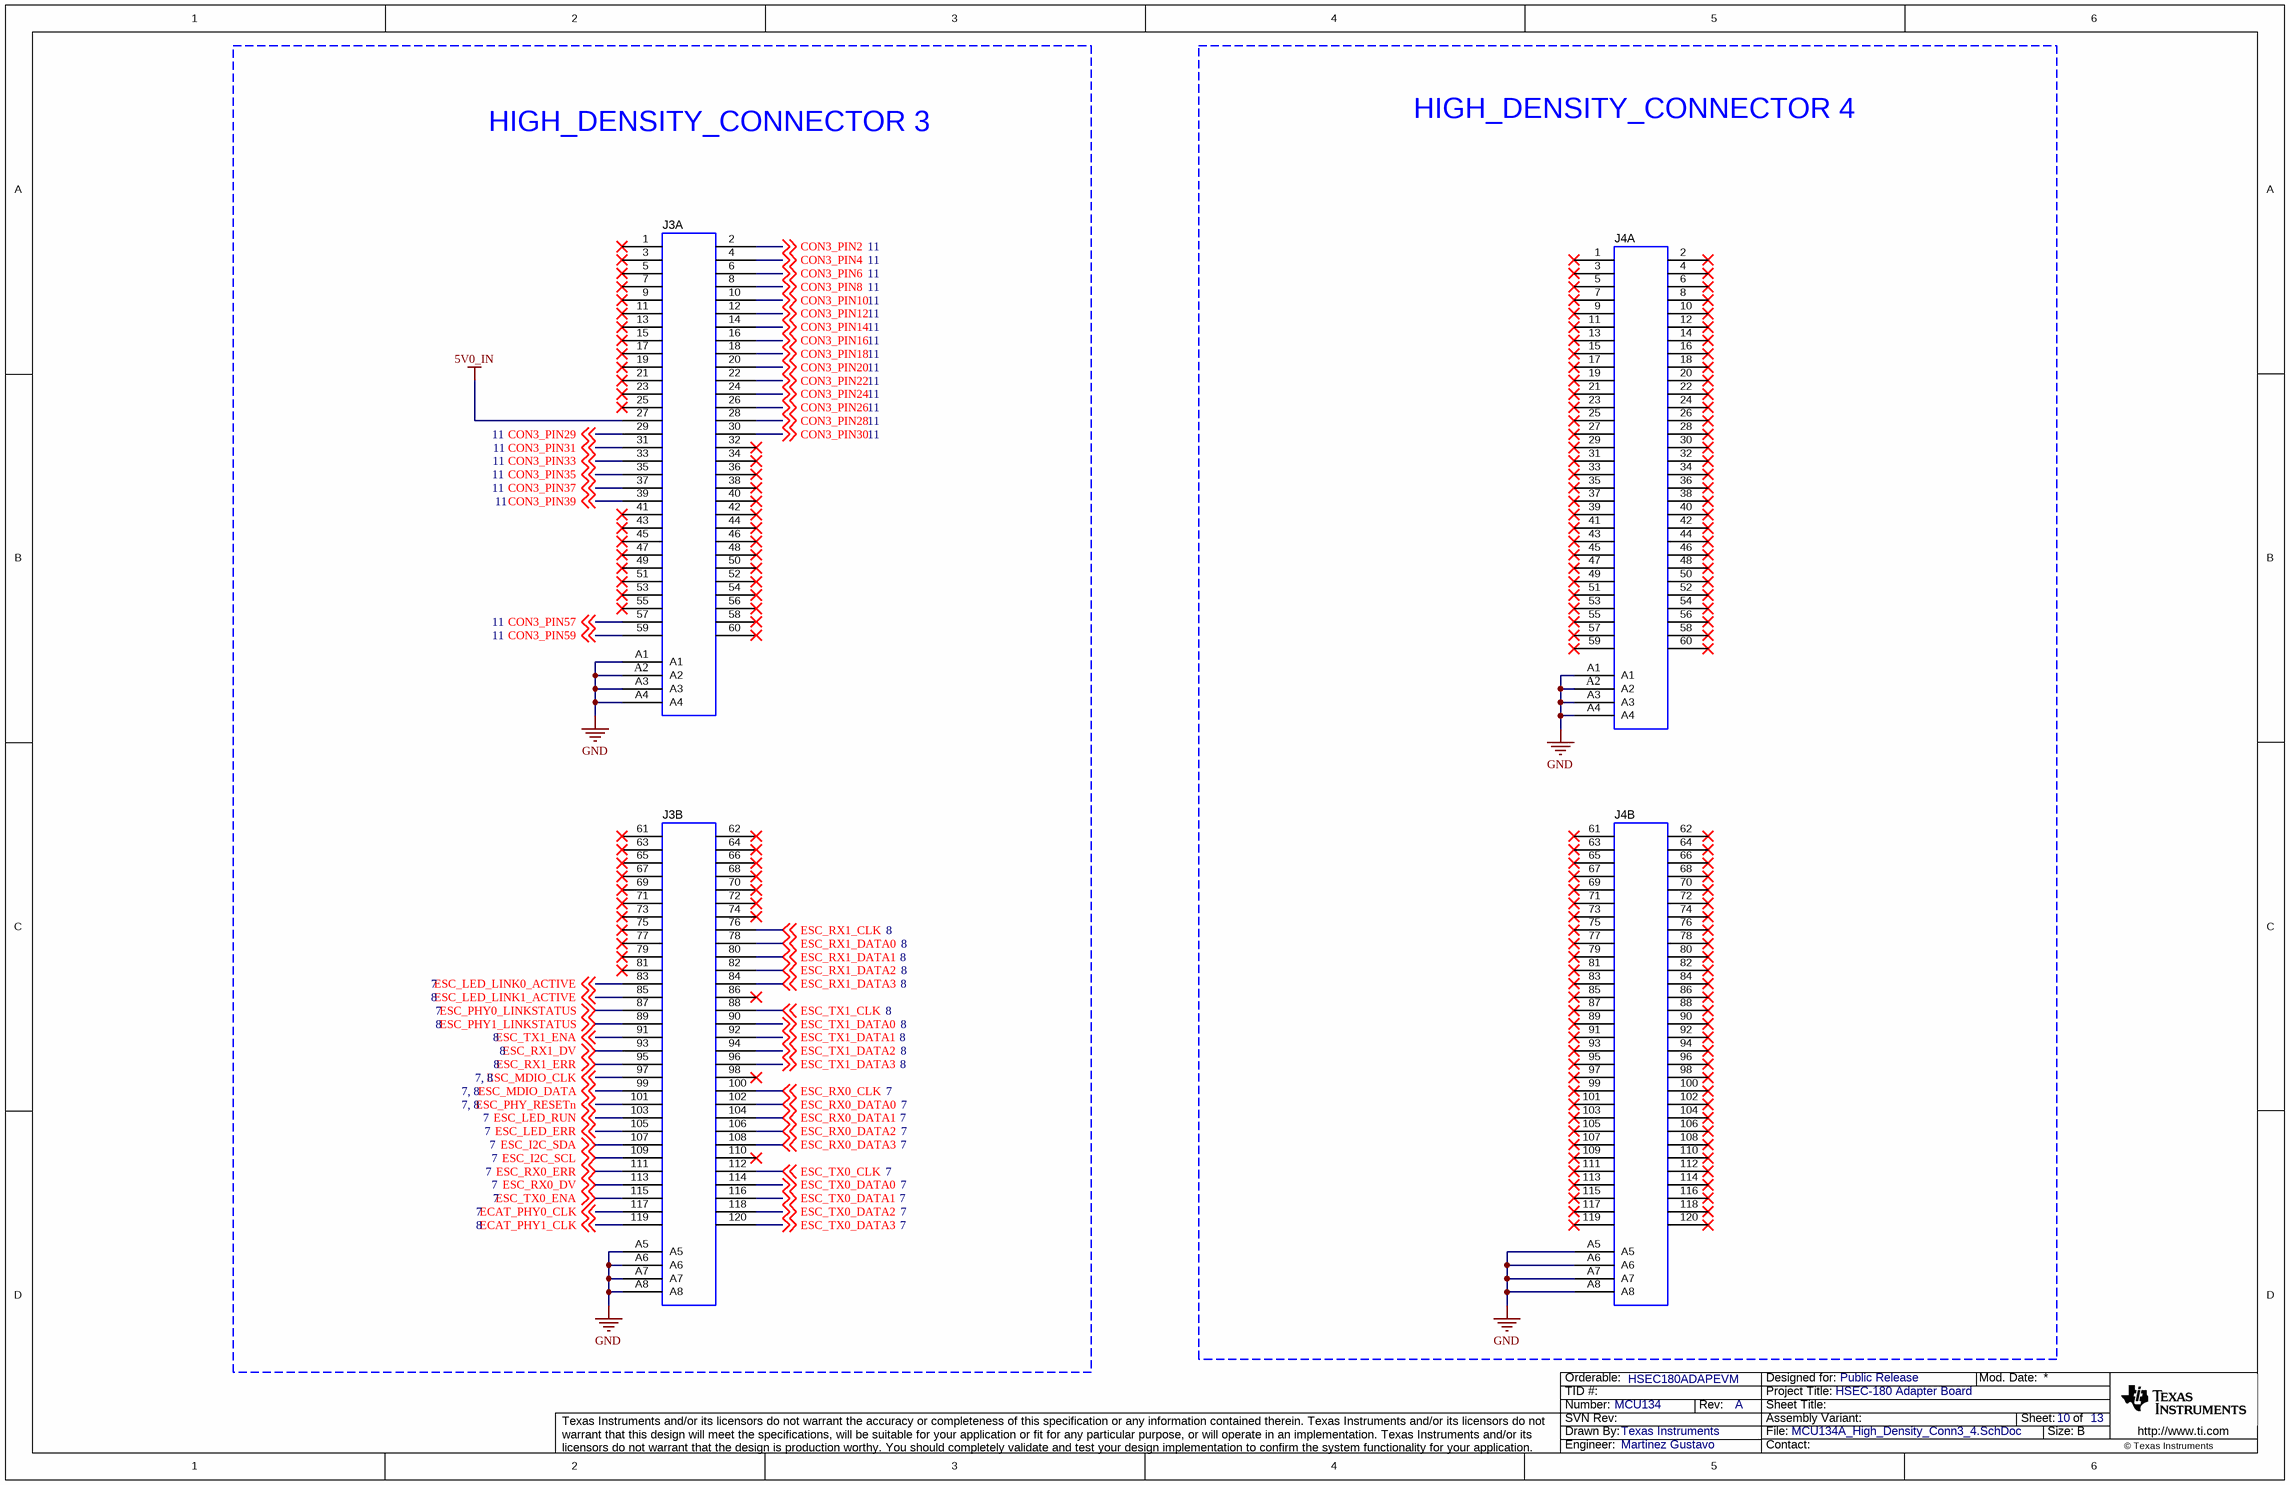
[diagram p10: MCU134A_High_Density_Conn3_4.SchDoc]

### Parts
J3  QTH-060-01-L-D-A  [SAMTEC_QTH-060-01-L-D-A]  (value not drawn)  (parts A,B of 2)
J4  QTH-060-01-L-D-A  [SAMTEC_QTH-060-01-L-D-A]  (value not drawn)  (parts A,B of 2)

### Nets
5V0_IN: J3.27
GND: J3.A1 J3.A2 J3.A3 J3.A4 J3.A5 J3.A6 J3.A7 J3.A8 J4.A1 J4.A2 J4.A3 J4.A4 J4.A5 J4.A6 J4.A7 J4.A8
CON3_PIN2: J3.2 ; off-sheet CON3_PIN2
CON3_PIN4: J3.4 ; off-sheet CON3_PIN4
CON3_PIN6: J3.6 ; off-sheet CON3_PIN6
CON3_PIN8: J3.8 ; off-sheet CON3_PIN8
CON3_PIN10: J3.10 ; off-sheet CON3_PIN10
CON3_PIN12: J3.12 ; off-sheet CON3_PIN12
CON3_PIN14: J3.14 ; off-sheet CON3_PIN14
CON3_PIN16: J3.16 ; off-sheet CON3_PIN16
CON3_PIN18: J3.18 ; off-sheet CON3_PIN18
CON3_PIN20: J3.20 ; off-sheet CON3_PIN20
CON3_PIN22: J3.22 ; off-sheet CON3_PIN22
CON3_PIN24: J3.24 ; off-sheet CON3_PIN24
CON3_PIN26: J3.26 ; off-sheet CON3_PIN26
CON3_PIN28: J3.28 ; off-sheet CON3_PIN28
CON3_PIN29: J3.29 ; off-sheet CON3_PIN29
CON3_PIN30: J3.30 ; off-sheet CON3_PIN30
CON3_PIN31: J3.31 ; off-sheet CON3_PIN31
CON3_PIN33: J3.33 ; off-sheet CON3_PIN33
CON3_PIN35: J3.35 ; off-sheet CON3_PIN35
CON3_PIN37: J3.37 ; off-sheet CON3_PIN37
CON3_PIN39: J3.39 ; off-sheet CON3_PIN39
CON3_PIN57: J3.57 ; off-sheet CON3_PIN57
CON3_PIN59: J3.59 ; off-sheet CON3_PIN59
ECAT_PHY0_CLK: J3.117 ; off-sheet ECAT_PHY0_CLK
ECAT_PHY1_CLK: J3.119 ; off-sheet ECAT_PHY1_CLK
ESC_I2C_SCL: J3.109 ; off-sheet ESC_I2C_SCL
ESC_I2C_SDA: J3.107 ; off-sheet ESC_I2C_SDA
ESC_LED_ERR: J3.105 ; off-sheet ESC_LED_ERR
ESC_LED_LINK0_ACTIVE: J3.83 ; off-sheet ESC_LED_LINK0_ACTIVE
ESC_LED_LINK1_ACTIVE: J3.85 ; off-sheet ESC_LED_LINK1_ACTIVE
ESC_LED_RUN: J3.103 ; off-sheet ESC_LED_RUN
ESC_MDIO_CLK: J3.97 ; off-sheet ESC_MDIO_CLK
ESC_MDIO_DATA: J3.99 ; off-sheet ESC_MDIO_DATA
ESC_PHY0_LINKSTATUS: J3.87 ; off-sheet ESC_PHY0_LINKSTATUS
ESC_PHY1_LINKSTATUS: J3.89 ; off-sheet ESC_PHY1_LINKSTATUS
ESC_PHY_RESETn: J3.101 ; off-sheet ESC_PHY_RESETn
ESC_RX0_CLK: J3.100 ; off-sheet ESC_RX0_CLK
ESC_RX0_DATA0: J3.102 ; off-sheet ESC_RX0_DATA0
ESC_RX0_DATA1: J3.104 ; off-sheet ESC_RX0_DATA1
ESC_RX0_DATA2: J3.106 ; off-sheet ESC_RX0_DATA2
ESC_RX0_DATA3: J3.108 ; off-sheet ESC_RX0_DATA3
ESC_RX0_DV: J3.113 ; off-sheet ESC_RX0_DV
ESC_RX0_ERR: J3.111 ; off-sheet ESC_RX0_ERR
ESC_RX1_CLK: J3.76 ; off-sheet ESC_RX1_CLK
ESC_RX1_DATA0: J3.78 ; off-sheet ESC_RX1_DATA0
ESC_RX1_DATA1: J3.80 ; off-sheet ESC_RX1_DATA1
ESC_RX1_DATA2: J3.82 ; off-sheet ESC_RX1_DATA2
ESC_RX1_DATA3: J3.84 ; off-sheet ESC_RX1_DATA3
ESC_RX1_DV: J3.93 ; off-sheet ESC_RX1_DV
ESC_RX1_ERR: J3.95 ; off-sheet ESC_RX1_ERR
ESC_TX0_CLK: J3.112 ; off-sheet ESC_TX0_CLK
ESC_TX0_DATA0: J3.114 ; off-sheet ESC_TX0_DATA0
ESC_TX0_DATA1: J3.116 ; off-sheet ESC_TX0_DATA1
ESC_TX0_DATA2: J3.118 ; off-sheet ESC_TX0_DATA2
ESC_TX0_DATA3: J3.120 ; off-sheet ESC_TX0_DATA3
ESC_TX0_ENA: J3.115 ; off-sheet ESC_TX0_ENA
ESC_TX1_CLK: J3.88 ; off-sheet ESC_TX1_CLK
ESC_TX1_DATA0: J3.90 ; off-sheet ESC_TX1_DATA0
ESC_TX1_DATA1: J3.92 ; off-sheet ESC_TX1_DATA1
ESC_TX1_DATA2: J3.94 ; off-sheet ESC_TX1_DATA2
ESC_TX1_DATA3: J3.96 ; off-sheet ESC_TX1_DATA3
ESC_TX1_ENA: J3.91 ; off-sheet ESC_TX1_ENA

Not connected (* = marked no-connect by the designer): J3 1* 3* 5* 7* 9* 11* 13* 15* 17* 19* 21* 23* 25* 32* 34* 36* 38* 40* 41* 42* 43* 44* 45* 46* 47* 48* 49* 50* 51* 52* 53* 54* 55* 56* 58* 60* 61* 62* 63* 64* 65* 66* 67* 68* 69* 70* 71* 72* 73* 74* 75* 77* 79* 81* 86* 98* 110*; J4 1* 2* 3* 4* 5* 6* 7* 8* 9* 10* 11* 12* 13* 14* 15* 16* 17* 18* 19* 20* 21* 22* 23* 24* 25* 26* 27* 28* 29* 30* 31* 32* 33* 34* 35* 36* 37* 38* 39* 40* 41* 42* 43* 44* 45* 46* 47* 48* 49* 50* 51* 52* 53* 54* 55* 56* 57* 58* 59* 60* 61* 62* 63* 64* 65* 66* 67* 68* 69* 70* 71* 72* 73* 74* 75* 76* 77* 78* 79* 80* 81* 82* 83* 84* 85* 86* 87* 88* 89* 90* 91* 92* 93* 94* 95* 96* 97* 98* 99* 100* 101* 102* 103* 104* 105* 106* 107* 108* 109* 110* 111* 112* 113* 114* 115* 116* 117* 118* 119* 120*

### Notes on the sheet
- HIGH_DENSITY_CONNECTOR 3
- HIGH_DENSITY_CONNECTOR 4

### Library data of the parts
J3 J4 = CMP-0056023-2: as J1 on sheet MCU134A_High_Density_Conn1_2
